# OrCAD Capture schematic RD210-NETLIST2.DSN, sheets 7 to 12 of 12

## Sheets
7 6: size Custom
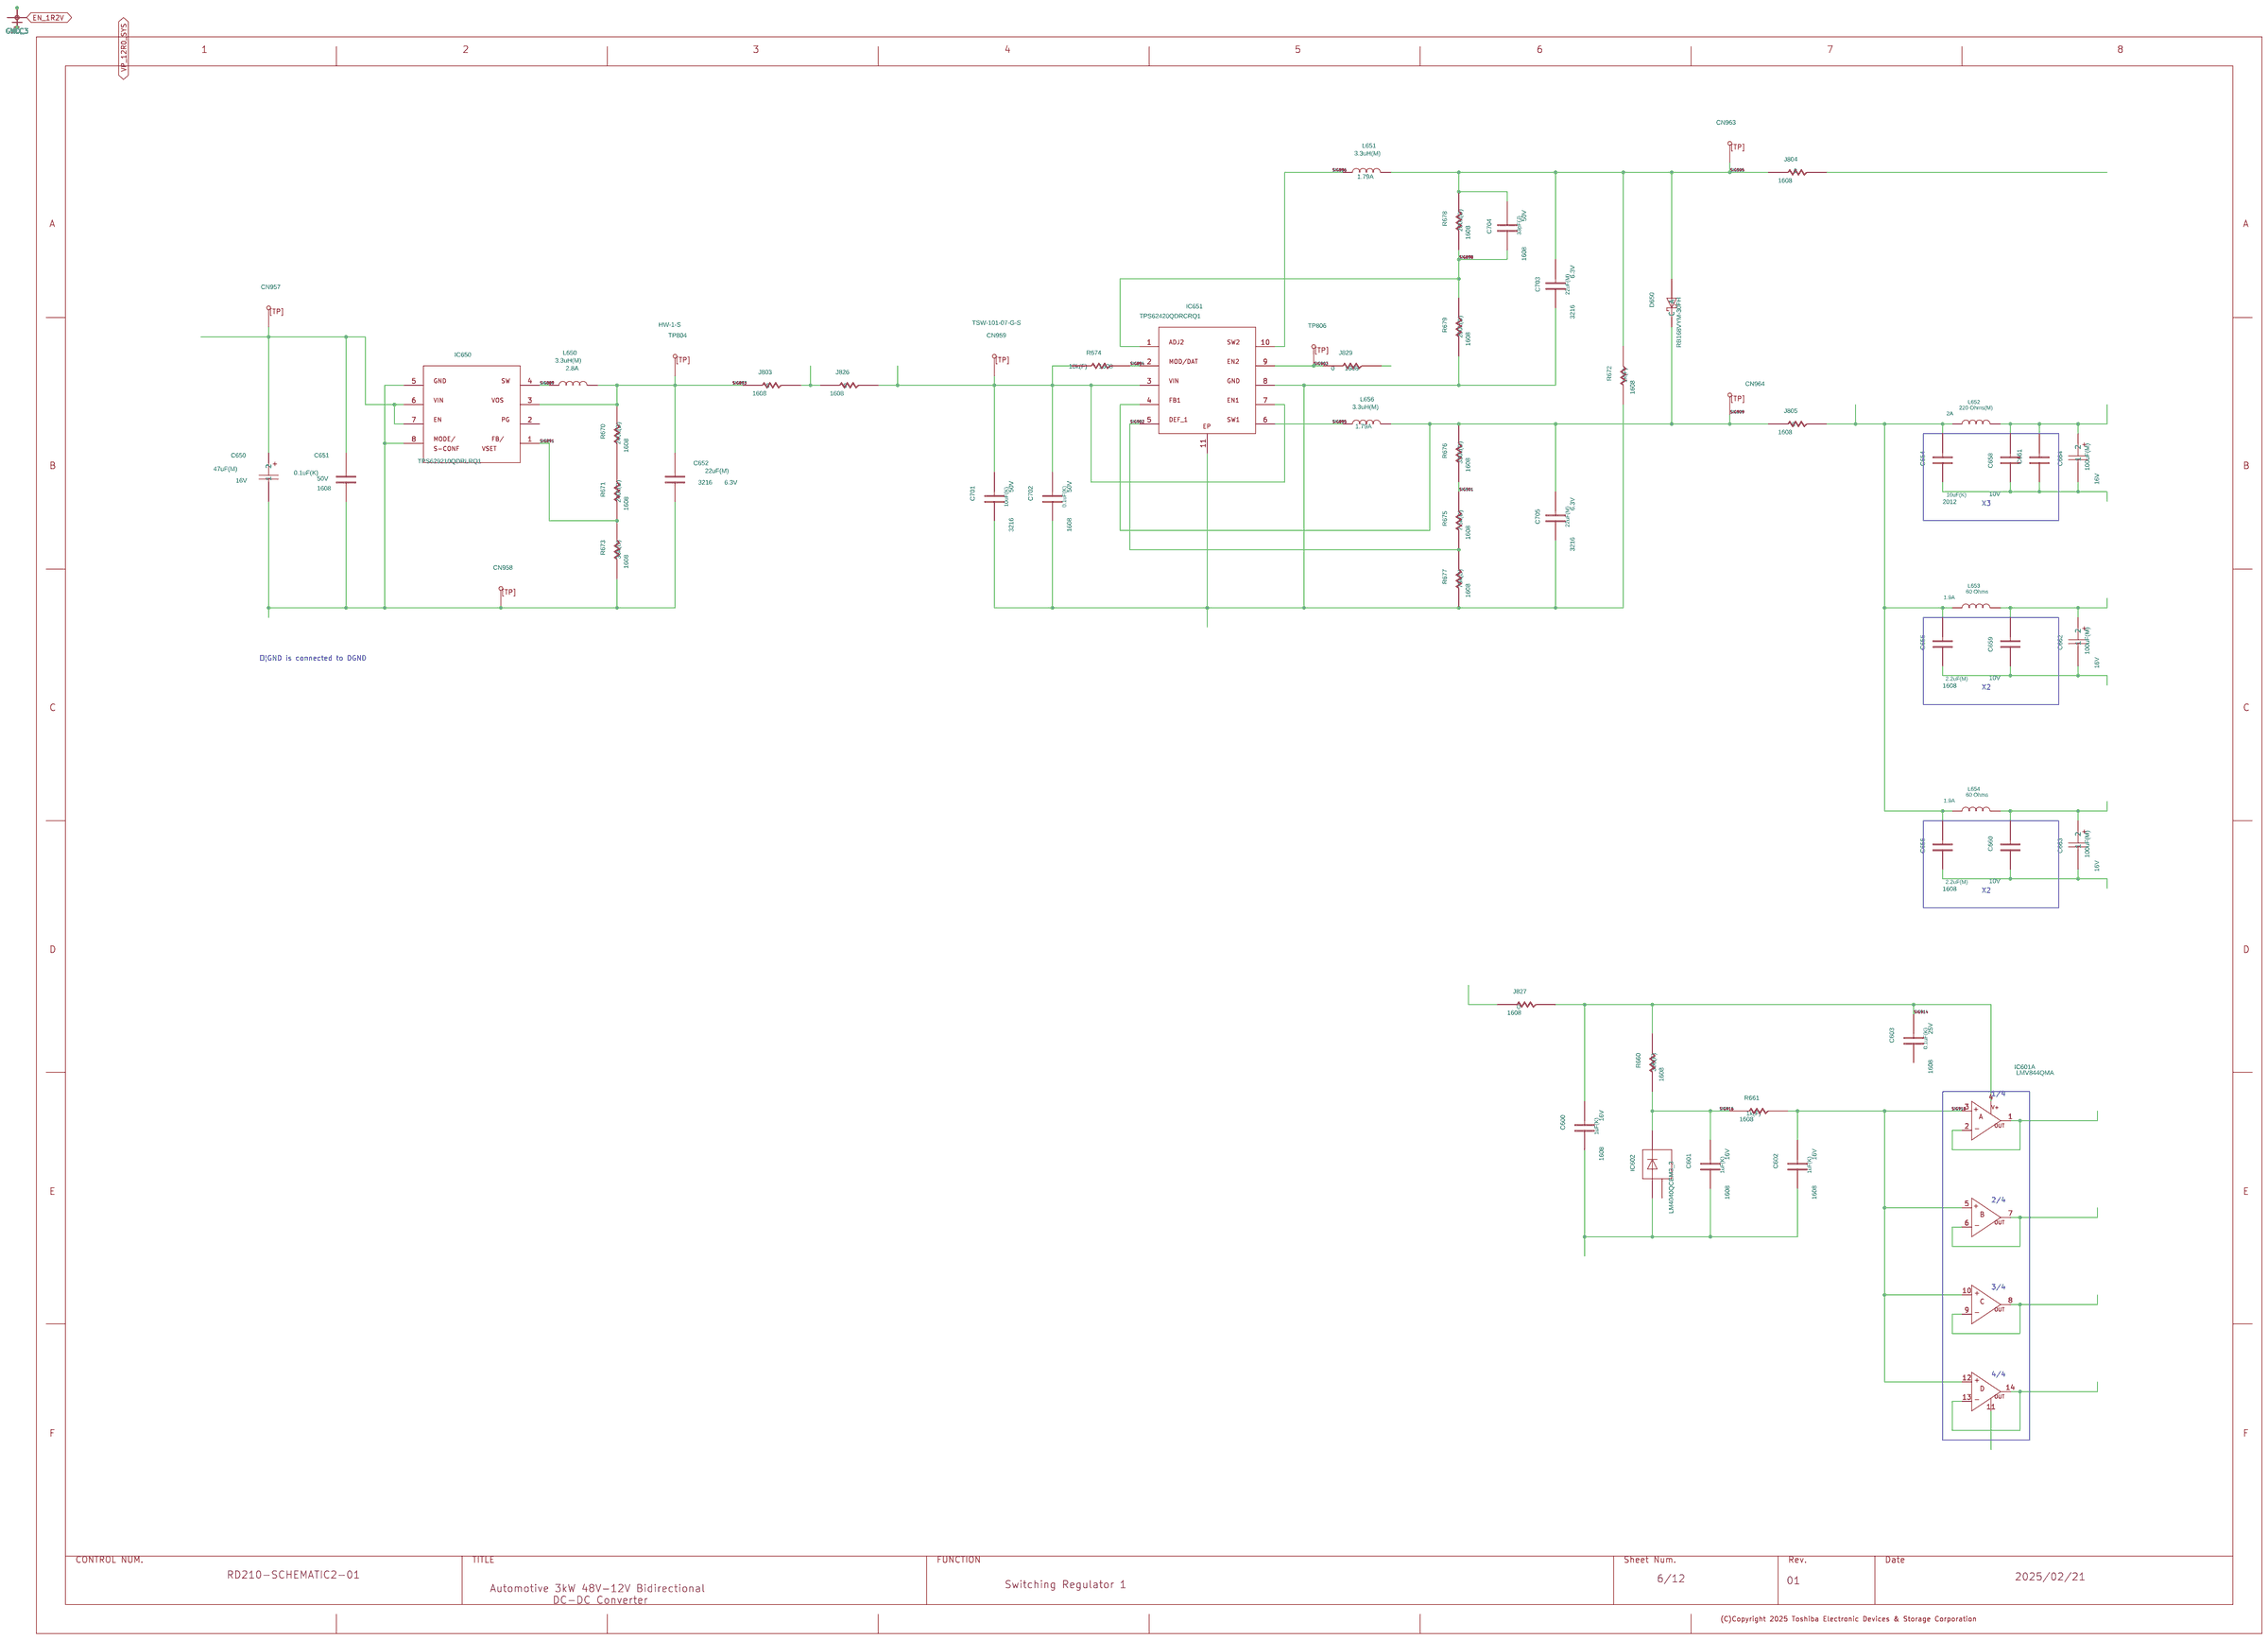
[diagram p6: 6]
8 5: size Custom
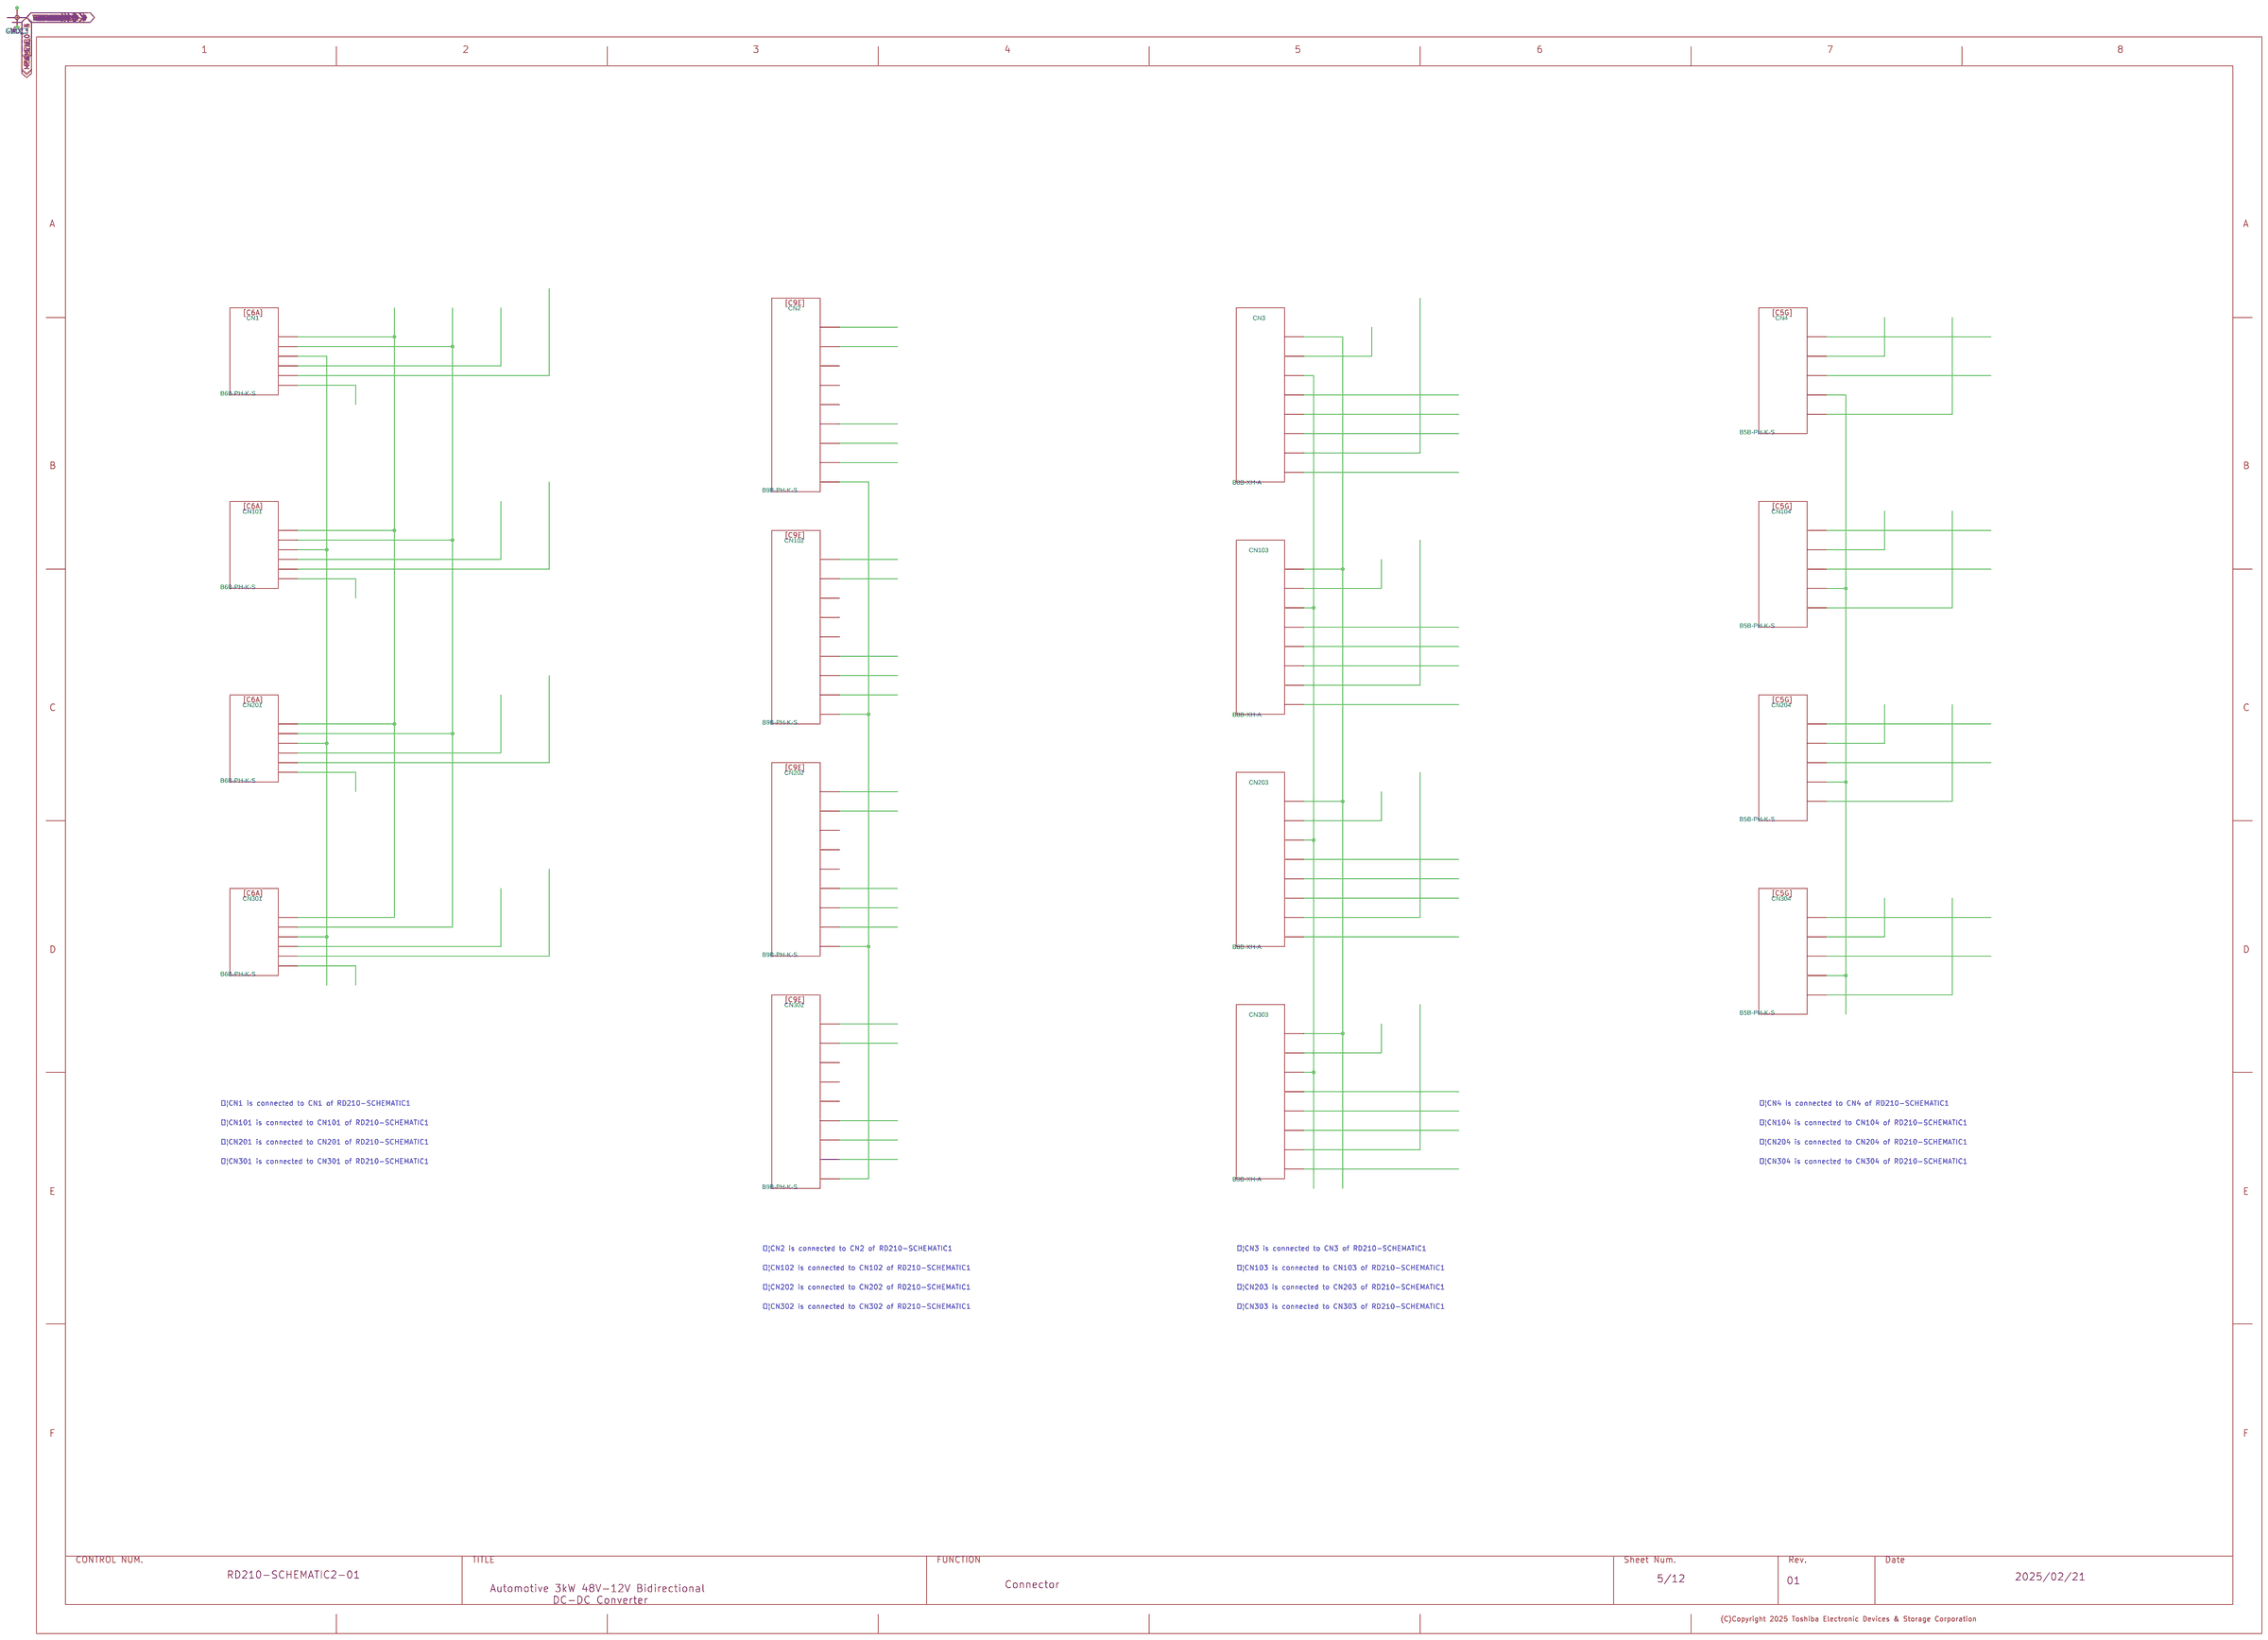
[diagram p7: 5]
9 4: size Custom
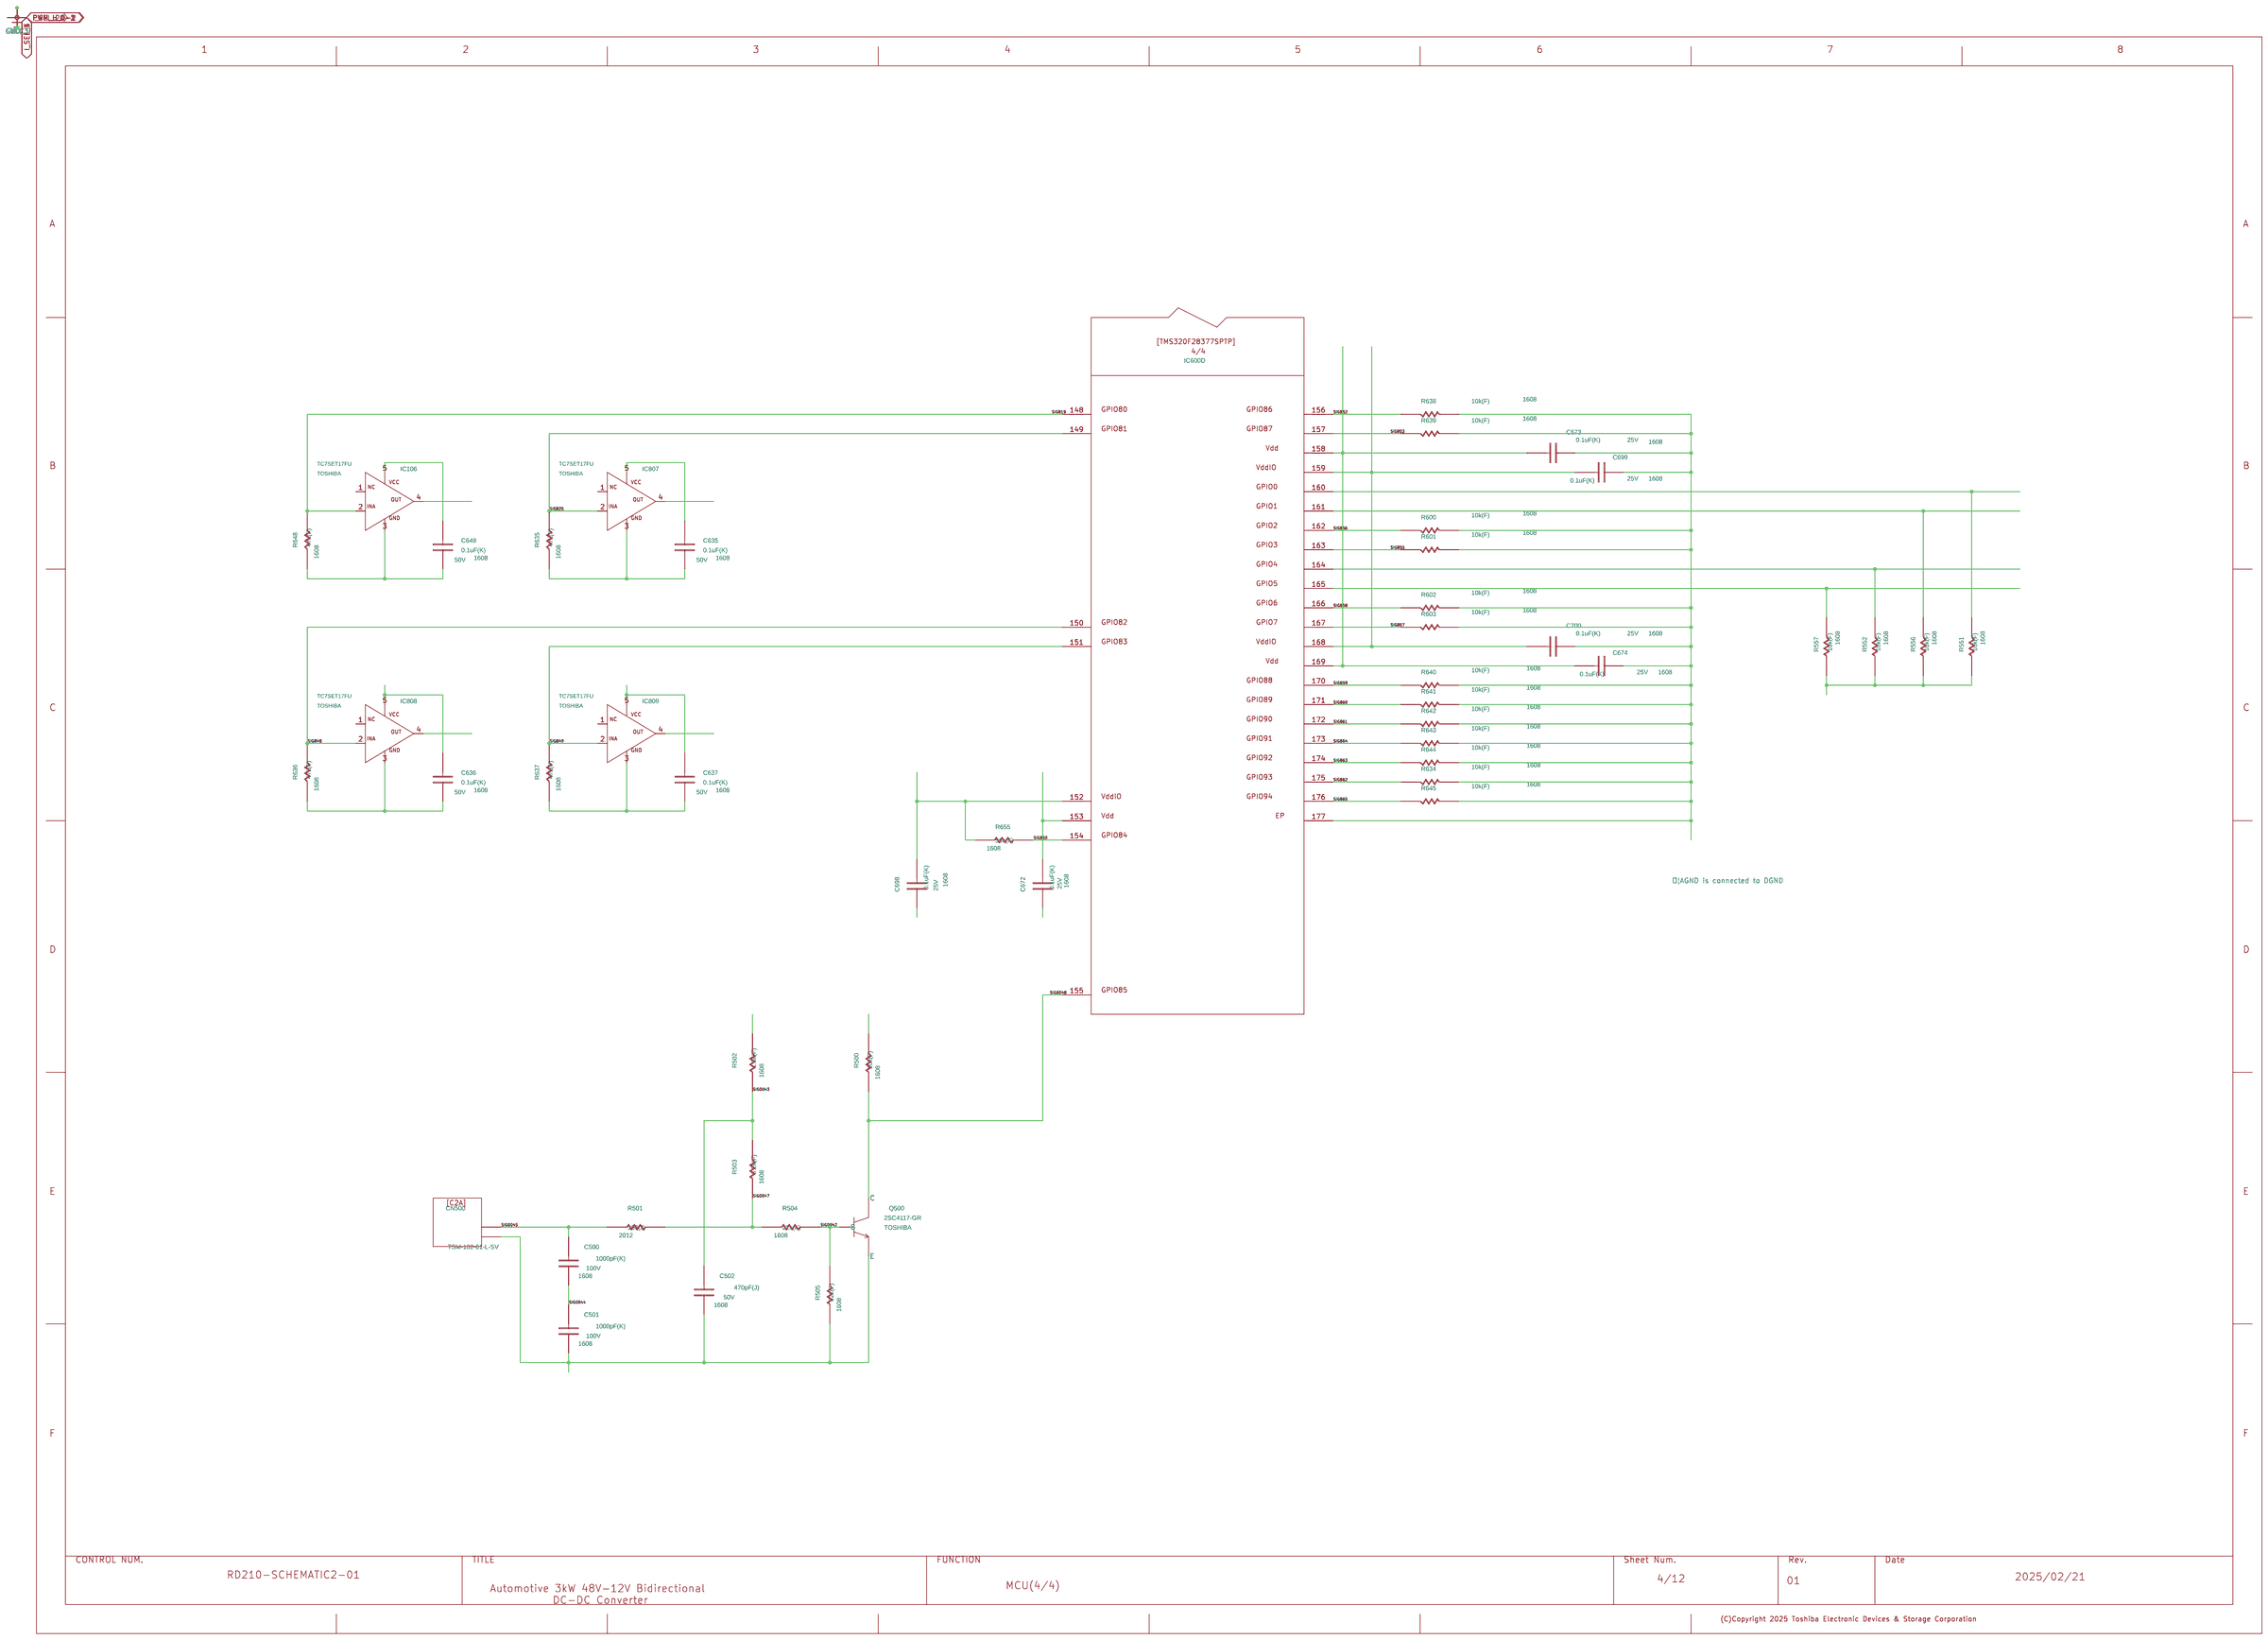
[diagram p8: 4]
10 3: size Custom
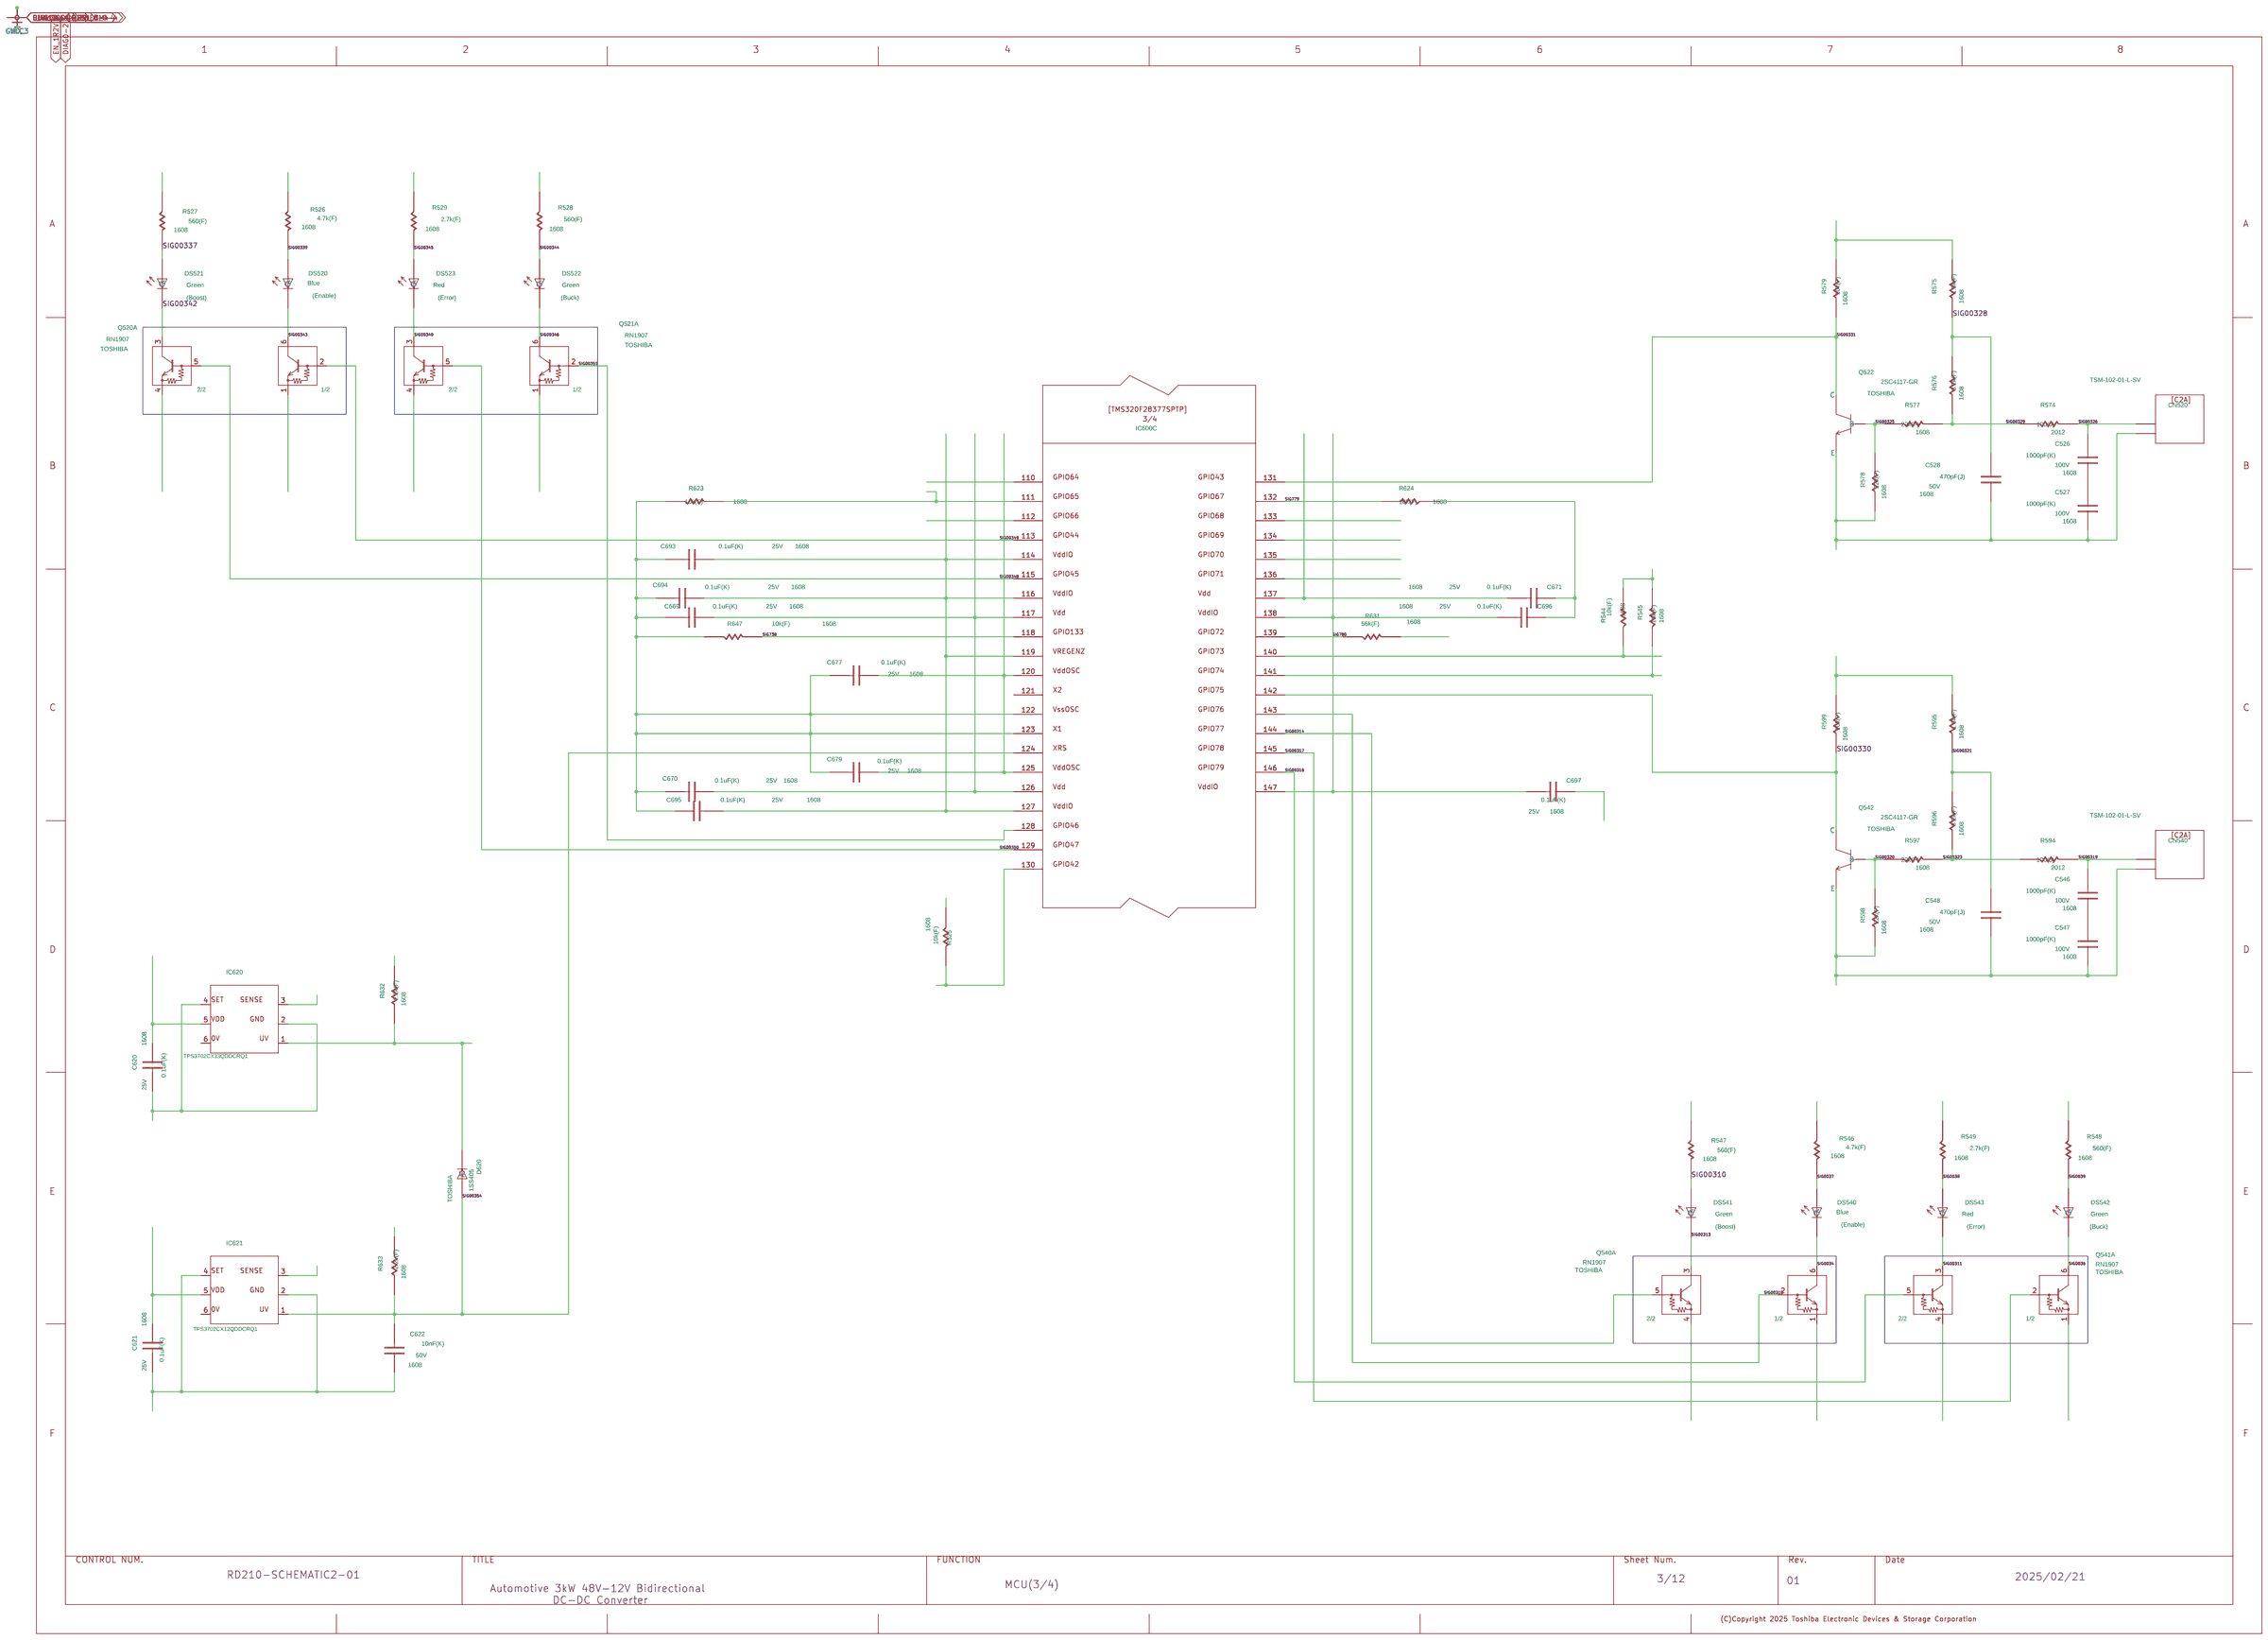
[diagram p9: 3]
11 2: size Custom
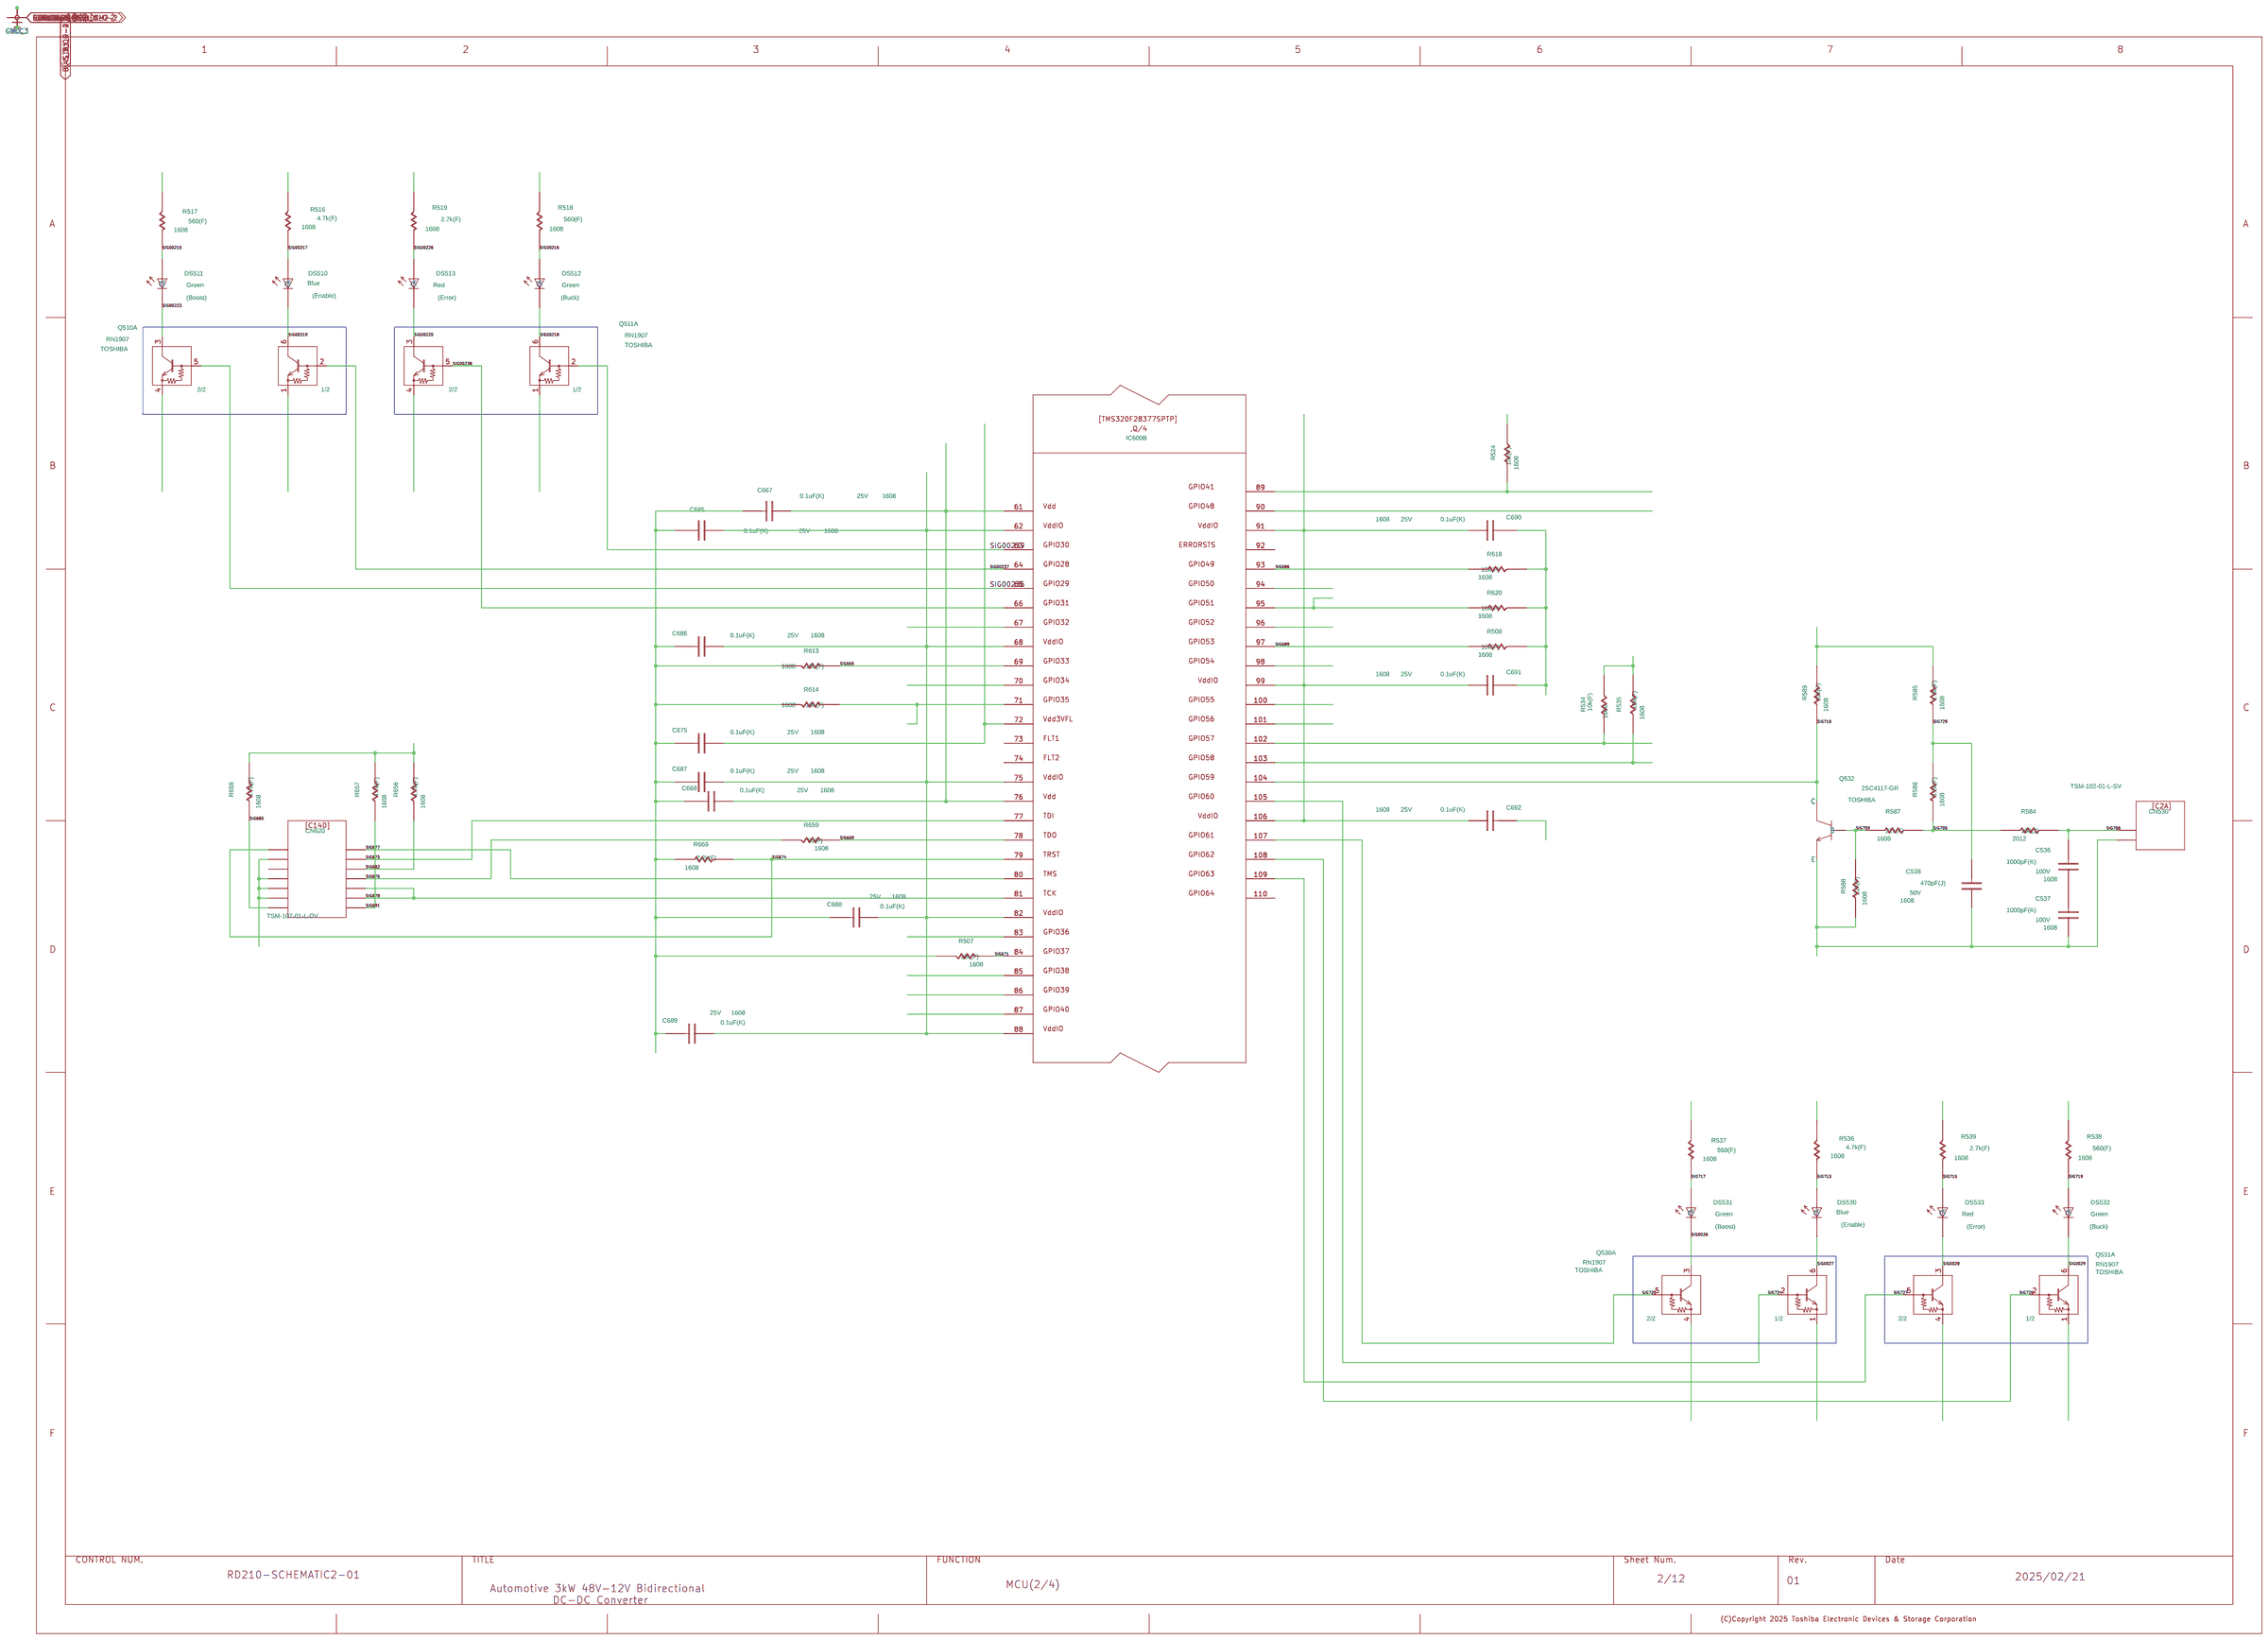
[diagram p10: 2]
12 1: size Custom
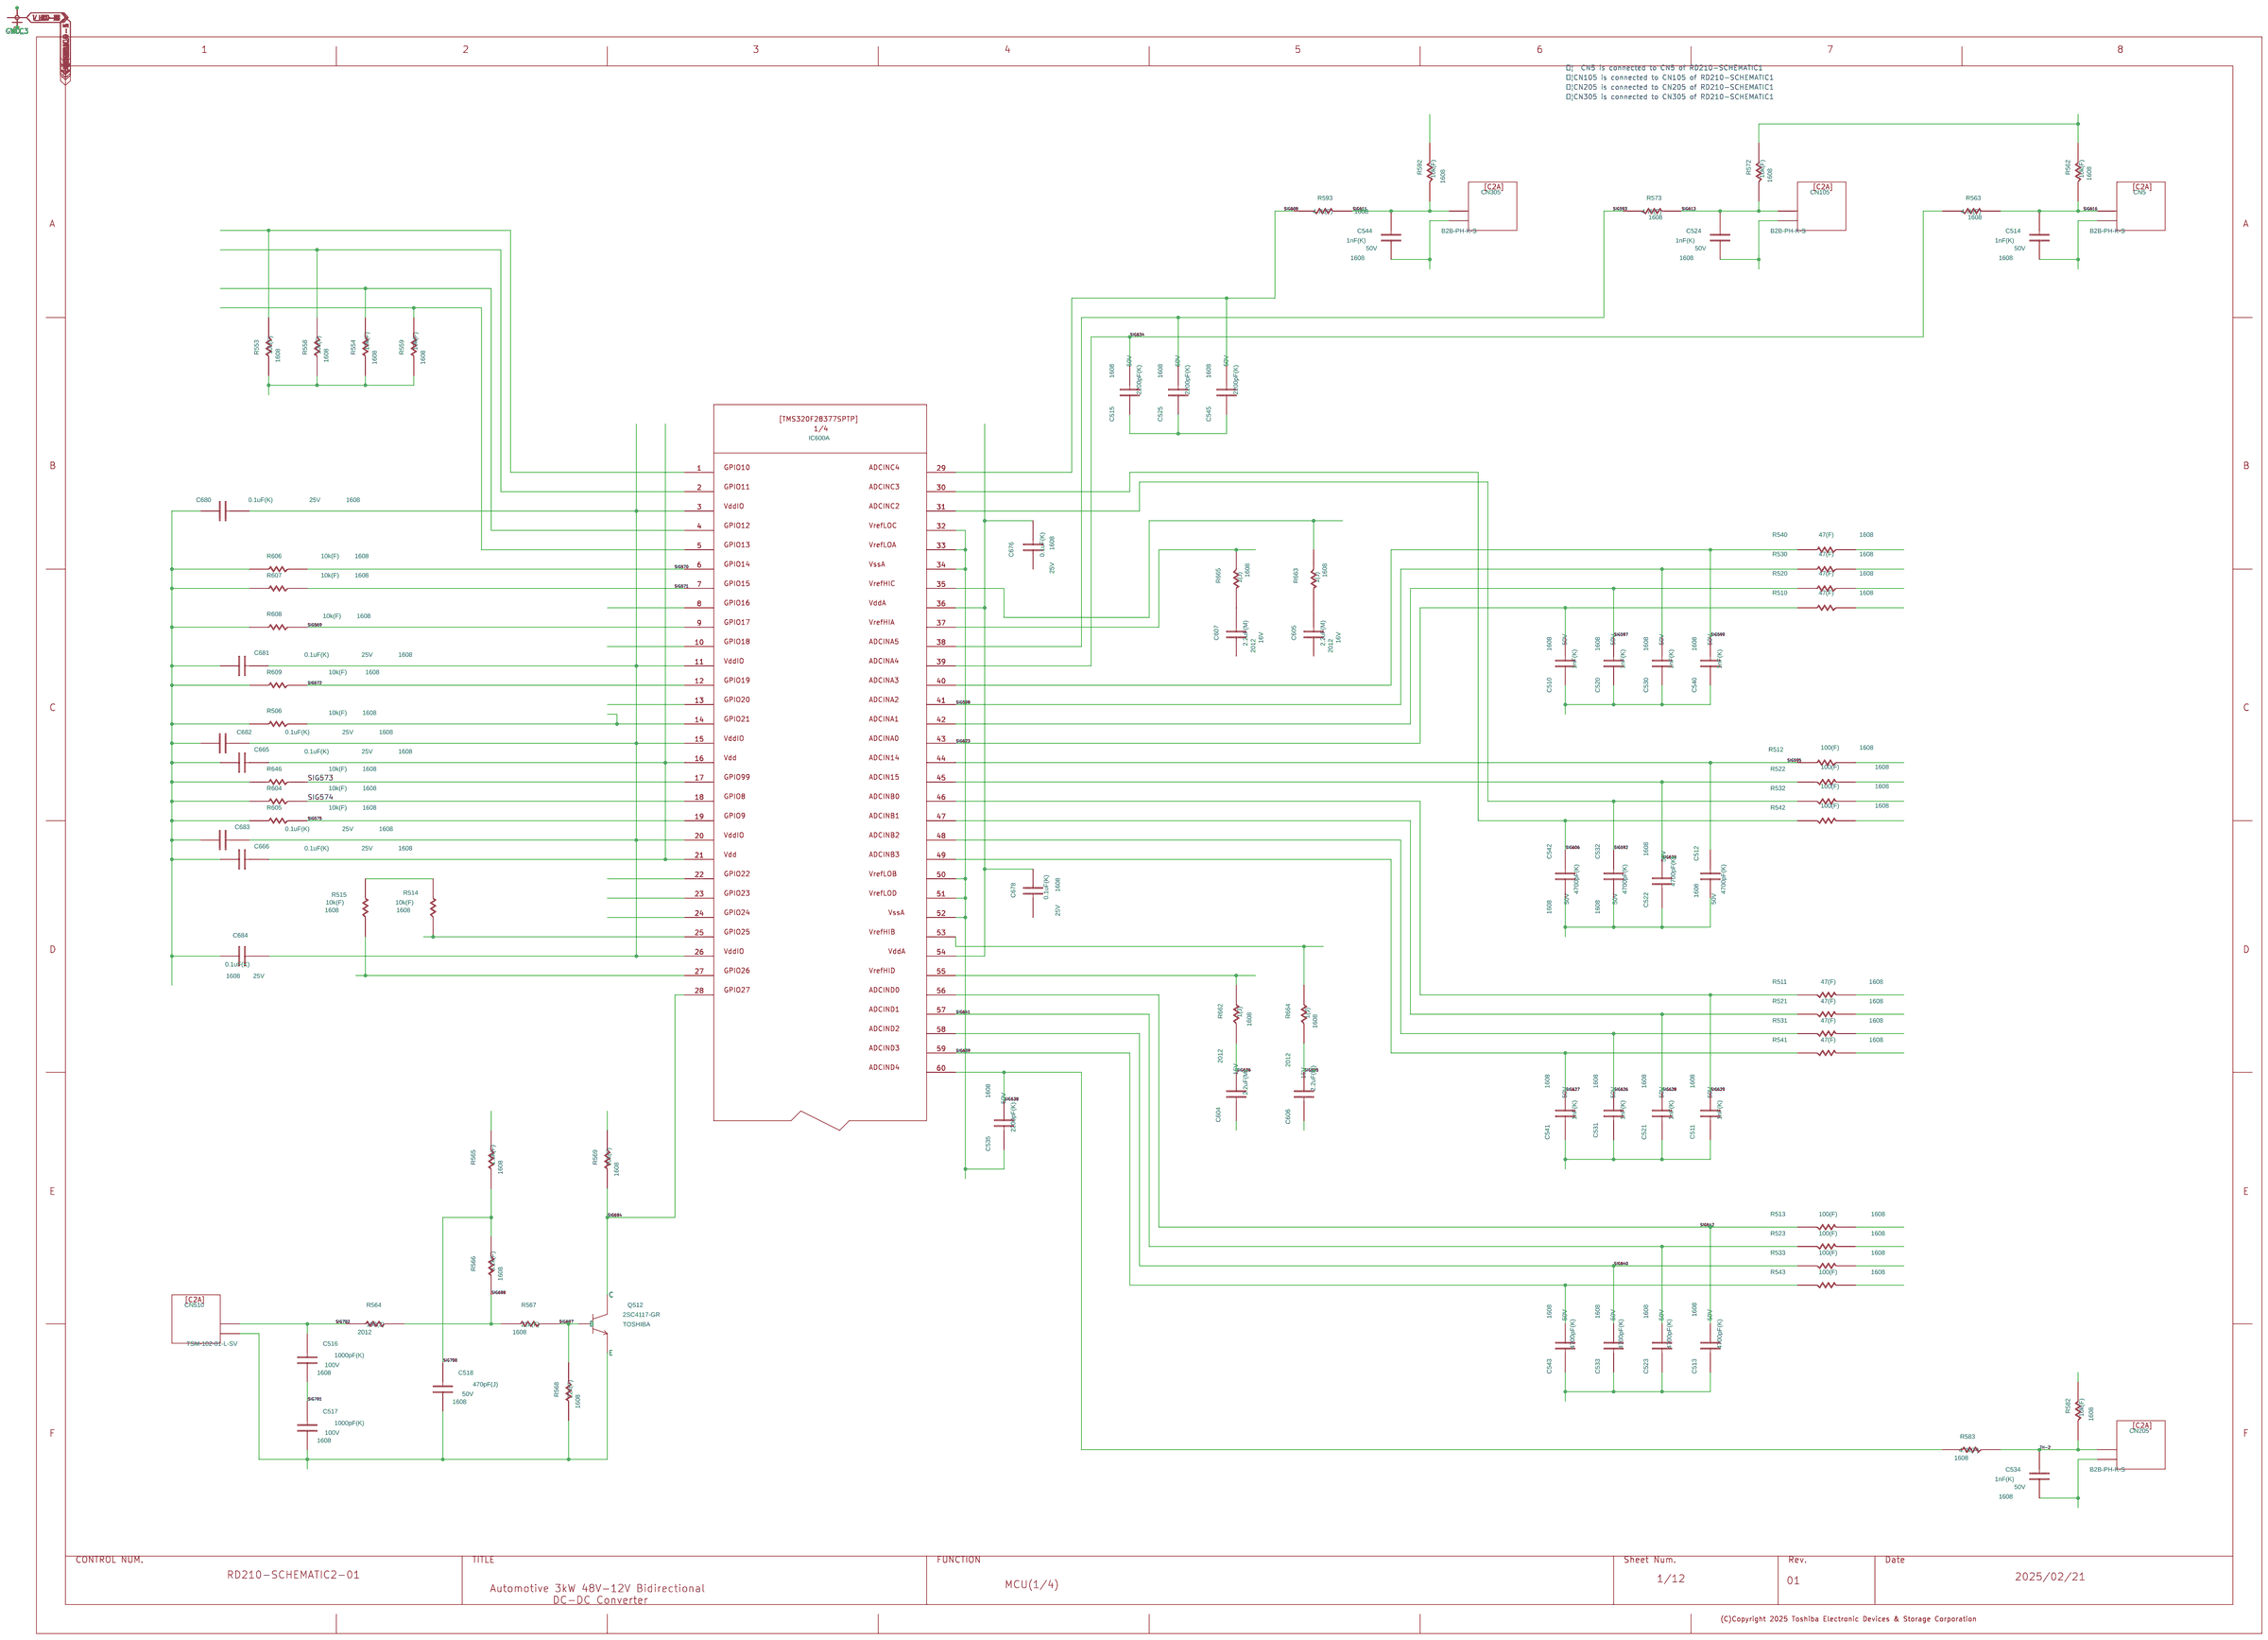
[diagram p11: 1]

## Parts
sheet 1
C510  C
C511  C
C512  C
C513  C
C514  C
C515  C
C516  C
C517  C
C518  C
C520  C
C521  C
C522  C
C523  C
C524  C
C525  C
C530  C
C531  C
C532  C
C533  C
C534  C
C535  C
C540  C
C541  C
C542  C
C543  C
C544  C
C545  C
C604  C
C605  C
C606  C
C607  C
C665  C
C666  C
C676  C
C678  C
C680  C
C681  C
C682  C
C683  C
C684  C
CN5  C2A
CN105  C2A
CN205  C2A
CN305  C2A
CN510  C2A
Q512  TRN
R506  R
R510  R
R511  R
R512  R
R513  R
R514  R
R515  R
R520  R
R521  R
R522  R
R523  R
R530  R
R531  R
R532  R
R533  R
R540  R
R541  R
R542  R
R543  R
R553  R
R554  R
R558  R
R559  R
R562  R
R563  R
R564  R
R565  R
R566  R
R567  R
R568  R
R569  R
R572  R
R573  R
R582  R
R583  R
R592  R
R593  R
R604  R
R605  R
R606  R
R607  R
R608  R
R609  R
R646  R
R662  R
R663  R
R664  R
R665  R
U?#11  WAKU_DEF_A3
sheet 2
C536  C
C537  C
C538  C
C667  C
C668  C
C675  C
C685  C
C686  C
C687  C
C688  C
C689  C
C690  C
C691  C
C692  C
CN530  C2A
CN620  C14D
DS510  LED
DS511  LED
DS512  LED
DS513  LED
DS530  LED
DS531  LED
DS532  LED
DS533  LED
Q510  RN1907_Q1  (sections A,B)
Q511  RN1907_Q1  (sections A,B)
Q530  RN1907_Q1  (sections A,B)
Q531  RN1907_Q1  (sections A,B)
Q532  TRN
R507  R
R508  R
R516  R
R517  R
R518  R
R519  R
R524  R
R534  R
R535  R
R536  R
R537  R
R538  R
R539  R
R584  R
R585  R
R586  R
R587  R
R588  R
R589  R
R613  R
R614  R
R618  R
R620  R
R656  R
R657  R
R658  R
R659  R
R669  R
U?#10  WAKU_DEF_A3
sheet 3
C526  C
C527  C
C528  C
C546  C
C547  C
C548  C
C620  C
C621  C
C622  C
C669  C
C670  C
C671  C
C677  C
C679  C
C693  C
C694  C
C695  C
C696  C
C697  C
CN520  C2A
CN540  C2A
D620  D
DS520  LED
DS521  LED
DS522  LED
DS523  LED
DS540  LED
DS541  LED
DS542  LED
DS543  LED
IC620  TPS3702CX12QDDCRQ1
IC621  TPS3702CX12QDDCRQ1
Q520  RN1907_Q1  (sections A,B)
Q521  RN1907_Q1  (sections A,B)
Q522  TRN
Q540  RN1907_Q1  (sections A,B)
Q541  RN1907_Q1  (sections A,B)
Q542  TRN
R525  R
R526  R
R527  R
R528  R
R529  R
R544  R
R545  R
R546  R
R547  R
R548  R
R549  R
R574  R
R575  R
R576  R
R577  R
R578  R
R579  R
R594  R
R595  R
R596  R
R597  R
R598  R
R599  R
R623  R
R624  R
R631  R
R632  R
R633  R
R647  R
U?#9  WAKU_DEF_A3
sheet 4
C500  C
C501  C
C502  C
C635  C
C636  C
C637  C
C648  C
C672  C
C673  C
C674  C
C698  C
C699  C
C700  C
CN500  C2A
IC106  TC7SET17FU
IC600  TMS320F28377SPTP_1  (sections A,B,C,D)
IC807  TC7SET17FU
IC808  TC7SET17FU
IC809  TC7SET17FU
Q500  TRN
R500  R
R501  R
R502  R
R503  R
R504  R
R505  R
R551  R
R552  R
R556  R
R557  R
R600  R
R601  R
R602  R
R603  R
R634  R
R635  R
R636  R
R637  R
R638  R
R639  R
R640  R
R641  R
R642  R
R643  R
R644  R
R645  R
R648  R
R655  R
U?#8  WAKU_DEF_A3
sheet 5
CN1  C6A
CN2  C9E
CN3  B8B-XH-A
CN4  C5G
CN101  C6A
CN102  C9E
CN103  B8B-XH-A
CN104  C5G
CN201  C6A
CN202  C9E
CN203  B8B-XH-A
CN204  C5G
CN301  C6A
CN302  C9E
CN303  B8B-XH-A
CN304  C5G
U?#7  WAKU_DEF_A3
sheet 6
C600  C
C601  C
C602  C
C603  C
C650  CP
C651  C
C652  C
C654  C
C655  C
C656  C
C658  C
C659  C
C660  C
C661  C
C662  CP
C663  CP
C664  CP
C701  C
C702  C
C703  C
C704  C
C705  C
CN957  TP
CN958  TP
CN959  TP
CN963  TP
CN964  TP
D650  SBD
IC601  LMV844QMA_1  (sections A,B,C,D)
IC602  LM4040QCEM3_3
IC650  TPS629210QDRLRQ1
IC651  TPS62420QDRCRQ1
J803  R
J804  R
J805  R
J826  R
J827  R
J829  R
L650  L
L651  L
L652  L
L653  L
L654  L
L656  L
R660  R
R661  R
R670  R
R671  R
R672  R
R673  R
R674  R
R675  R
R676  R
R677  R
R678  R
R679  R
TP804  TP
TP806  TP
U?#6  WAKU_DEF_A3

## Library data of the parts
C510 C511 C514 C520 C521 C524 C530 C531 C534 C540 C541 C544 = C: COMPONENTTYPE: 4; SIZECODESMD: 1608; VAL1: 1nF(K); VAL2: 50V
C512 C513 C522 C523 C532 C533 C542 C543 = C: COMPONENTTYPE: 4; SIZECODESMD: 1608; VAL1: 4700pF(K); VAL2: 50V
C515 C525 C535 C545 = C: COMPONENTTYPE: 4; SIZECODESMD: 1608; VAL1: 2200pF(K); VAL2: 50V
C500 C501 C516 C517 C526 C527 C536 C537 C546 C547 = C: COMPONENTTYPE: 4; SIZECODESMD: 1608; VAL1: 1000pF(K); VAL2: 100V
C502 C518 C528 C538 C548 = C: COMPONENTTYPE: 4; SIZECODESMD: 1608; VAL1: 470pF(J); VAL2: 50V
C604-C607 = C: COMPONENTTYPE: 4; SIZECODESMD: 2012; VAL1: 2.2uF(M); VAL2: 16V
C603 C620 C621 C665-C700 = C: COMPONENTTYPE: 4; SIZECODESMD: 1608; VAL1: 0.1uF(K); VAL2: 25V
CN5 CN105 CN205 CN305 = C2A: CDBNAME: CN; COMP: CN; COMPONENTTYPE: 4; VAL3: B2B-PH-K-S
CN500 CN510 CN520 CN530 CN540 = C2A: CDBNAME: CN; COMP: CN; COMPONENTTYPE: 4; VAL3: TSM-102-01-L-SV
Q500 Q512 Q522 Q532 Q542 = TRN: CDBNAME: Q; COMP: Q; COMPONENTTYPE: 4; USERCOMPTEXT3: TOSHIBA; VAL3: 2SC4117-GR
R500 R506-R508 R514 R515 R524 R525 R534 R535 R544 R545 R551-R554 R556-R559 R562 R569 R572 R579 R582 R589 R592 R599-R609 R613 R614 R618 R620 R623 R624 R634 R638-R647 R674 = R: COMPONENTTYPE: 4; SIZECODESMD: 1608; VAL1: 10k(F); VAL2: 200mW
R510 R511 R520 R521 R530 R531 R540 R541 = R: COMPONENTTYPE: 4; SIZECODESMD: 1608; VAL1: 47(F); VAL2: 200mW
R512 R513 R522 R523 R532 R533 R542 R543 = R: COMPONENTTYPE: 4; SIZECODESMD: 1608; VAL1: 100(F); VAL2: 200mW
R516 R526 R536 R546 R563 R573 R583 R593 R656-R658 = R: COMPONENTTYPE: 4; SIZECODESMD: 1608; VAL1: 4.7k(F); VAL2: 200mW
R501 R564 R574 R584 R594 = R: COMPONENTTYPE: 4; SIZECODESMD: 2012; VAL1: 100(J); VAL2: 250mW
R502 R565 R575 R585 R595 = R: COMPONENTTYPE: 4; SIZECODESMD: 1608; VAL1: 1.8k(F); VAL2: 333mW
R503 R566 R576 R586 R596 = R: COMPONENTTYPE: 4; SIZECODESMD: 1608; VAL1: 8.2k(F); VAL2: 333mW
R504 R505 R567 R568 R577 R578 R587 R588 R597 R598 = R: COMPONENTTYPE: 4; SIZECODESMD: 1608; VAL1: 22k(F); VAL2: 333mW
R662-R665 = R: COMPONENTTYPE: 4; SIZECODESMD: 1608; VAL1: 1(J); VAL2: 125mW
U?#11 = WAKU_DEF_A3: COMPONENTTYPE: 2; DATE: 2025/02/21; DRAWINGNUMBER: RD210-SCHEMATIC2-01; FUNCTION: MCU(1/4); REVISION: 01; SAVEAREA0: 185750,-43960,448537,75779; SAVECOUNT: 19; SHEETNUMBER: 1/12; SHTSAVECOUNT: 205; TITLE: Automotive 3kW 48V-12V Bidirectional / DC-DC Converter; UPDATEDATE: 2025.2.21; UPDATETIME: 06:59:19
CN620 = C14D: CDBNAME: CN; COMP: CN; COMPONENTTYPE: 4; VAL3: TSM-107-01-L-DV
DS510 DS520 DS530 DS540 = LED: CDBNAME: DS; COMP: DS; COMPONENTTYPE: 4; USERCOMPTEXT1: (Enable); VAL1: Blue; VAL3: KB_DELPS2.12
DS511 DS521 DS531 DS541 = LED: CDBNAME: DS; COMP: DS; COMPONENTTYPE: 4; USERCOMPTEXT1: (Boost); VAL1: Green; VAL3: KT_DELQS1.12
DS512 DS522 DS532 DS542 = LED: CDBNAME: DS; COMP: DS; COMPONENTTYPE: 4; USERCOMPTEXT1: (Buck); VAL1: Green; VAL3: KT_DELQS1.12
DS513 DS523 DS533 DS543 = LED: CDBNAME: DS; COMP: DS; COMPONENTTYPE: 4; USERCOMPTEXT1: (Error); VAL1: Red; VAL3: KS_DELQS1.12
Q510 Q520 Q521 Q540 Q541 = RN1907_Q1: CDBNAME: RN1907; COMP: RN1907; COMPONENTNAME: RN1907_1; COMPONENTTYPE: 8; CaptureCellPackProp: RN1907_Q1A; FUNCN: RN1907_1; USERCOMPTEXT1: 1/2; USERCOMPTEXT3: TOSHIBA; VAL3: RN1907
Q511 = RN1907_Q1: CDBNAME: RN1907; COMP: RN1907; COMPONENTNAME: RN1907_2; COMPONENTTYPE: 8; CaptureCellPackProp: RN1907_Q1B; FUNCN: RN1907_2; USERCOMPTEXT1: 2/2; USERCOMPTEXT3: TOSHIBA; VAL3: RN1907
Q530 Q531 = RN1907_Q1: CDBNAME: RN1907; COMP: RN1907; COMPONENTKIND: 101; COMPONENTNAME: RN1907_1; COMPONENTTYPE: 8; CaptureCellPackProp: RN1907_Q1A; FUNCN: RN1907_1; USERCOMPTEXT1: 1/2; USERCOMPTEXT3: TOSHIBA; VAL3: RN1907
R517 R518 R527 R528 R537 R538 R547 R548 = R: COMPONENTTYPE: 4; SIZECODESMD: 1608; VAL1: 560(F); VAL2: 200mW
R519 R529 R539 R549 = R: COMPONENTTYPE: 4; SIZECODESMD: 1608; VAL1: 2.7k(F); VAL2: 200mW
R659 = R: COMPONENTTYPE: 4; SIZECODESMD: 1608; VAL1: 39(F); VAL2: 200mW
R632 R633 R669 = R: COMPONENTTYPE: 4; SIZECODESMD: 1608; VAL1: 2.2k(F); VAL2: 200mW
U?#10 = WAKU_DEF_A3: AUTHOR: sptcae13; COMPONENTTYPE: 2; DATE: 2025/02/21; DRAWINGNUMBER: RD210-SCHEMATIC2-01; FUNCTION: MCU(2/4); REVISION: 01; SAVECOUNT: 19; SHEETNUMBER: 2/12; SHTSAVECOUNT: 79; TIME: 08:03:34; TITLE: Automotive 3kW 48V-12V Bidirectional / DC-DC Converter; UPDATEDATE: 2025.2.21; UPDATETIME: 13:38:15
C622 = C: COMPONENTTYPE: 4; SIZECODESMD: 1608; VAL1: 10nF(K); VAL2: 50V
D620 = D: COMPONENTTYPE: 4; USERCOMPTEXT3: TOSHIBA; VAL3: 1SS405
IC620 = TPS3702CX12QDDCRQ1: CDBNAME: IC; COMP: IC; COMPONENTKIND: 101; COMPONENTTYPE: 4; VAL3: TPS3702CX33QDDCRQ1
IC621 = TPS3702CX12QDDCRQ1: CDBNAME: IC; COMP: IC; COMPONENTKIND: 101; COMPONENTTYPE: 4
R631 R655 = R: COMPONENTTYPE: 4; SIZECODESMD: 1608; VAL1: 56k(F); VAL2: 200mW
U?#9 = WAKU_DEF_A3: AUTHOR: sptcae13; COMPONENTTYPE: 2; DATE: 2025/02/21; DRAWINGNUMBER: RD210-SCHEMATIC2-01; FUNCTION: MCU(3/4); REVISION: 01; SAVECOUNT: 19; SHEETNUMBER: 3/12; SHTSAVECOUNT: 66; TIME: 08:03:34; TITLE: Automotive 3kW 48V-12V Bidirectional / DC-DC Converter; UPDATEDATE: 2025.2.21; UPDATETIME: 12:28:01
C635-C637 C648 C651 C702 = C: COMPONENTTYPE: 4; SIZECODESMD: 1608; VAL1: 0.1uF(K); VAL2: 50V
IC106 IC807-IC809 = TC7SET17FU: CDBNAME: IC; COMP: IC; COMPONENTTYPE: 4; USERCOMPTEXT3: TOSHIBA
IC600 = TMS320F28377SPTP_1: CDBNAME: IC; COMP: IC; COMPONENTTYPE: 8; CaptureCellPackProp: TMS320F28377SPTP_1A; SAVEAREA0: -164425,-192040,236003,1269; USERCOMPTEXT3: TOSHIBA; VAL3: TMS320F28377SPTP; SAVECOUNT: 25
R635-R637 R648 = R: COMPONENTTYPE: 4; SIZECODESMD: 1608; VAL1: 47k(F); VAL2: 100mW
U?#8 = WAKU_DEF_A3: AUTHOR: sptcae13; COMPONENTTYPE: 2; DATE: 2025/02/21; DRAWINGNUMBER: RD210-SCHEMATIC2-01; FUNCTION: MCU(4/4); REVISION: 01; SAVECOUNT: 8; SHEETNUMBER: 4/12; SHTSAVECOUNT: 41; TIME: 17:43:31; TITLE: Automotive 3kW 48V-12V Bidirectional / DC-DC Converter; UPDATEDATE: 2025.2.21; UPDATETIME: 06:43:32
CN1 CN101 CN201 CN301 = C6A: CDBNAME: CN; COMP: CN; COMPONENTTYPE: 4; VAL3: B6B-PH-K-S
CN2 CN102 CN202 CN302 = C9E: CDBNAME: CN; COMP: CN; COMPONENTTYPE: 4; VAL3: B9B-PH-K-S
CN3 CN103 CN203 CN303 = B8B-XH-A: CDBNAME: CN; COMP: CN; COMPONENTTYPE: 4
CN4 CN104 CN204 CN304 = C5G: CDBNAME: CN; COMP: CN; COMPONENTTYPE: 4; VAL3: B5B-PH-K-S
U?#7 = WAKU_DEF_A3: AUTHOR: sptcae13; COMPONENTTYPE: 2; DATE: 2025/02/21; DRAWINGNUMBER: RD210-SCHEMATIC2-01; FUNCTION: Connector; REVISION: 01; SAVEAREA0: -45080,-4508,463680,304612; SAVECOUNT: 19; SHEETNUMBER: 5/12; SHTSAVECOUNT: 33; TIME: 09:45:21; TITLE: Automotive 3kW 48V-12V Bidirectional / DC-DC Converter; UPDATEDATE: 2025.2.21; UPDATETIME: 09:54:21
C600-C602 = C: COMPONENTTYPE: 4; SIZECODESMD: 1608; VAL1: 1uF(K); VAL2: 16V
C650 = CP: ADSCNVFLAG: ON; CDBNAME: C; COMP: C; COMPONENTTYPE: 4; GCOUNT: 1; ICX_PART_MODEL: CON_47U; MAXGCOUNT: 1; SQ_PART_MODEL: CON_47U; VAL1: 47uF(M); VAL2: 16V
C652 C703 C705 = C: COMPONENTTYPE: 4; SIZECODESMD: 3216; VAL1: 22uF(M); VAL2: 6.3V
C654 C658 C661 = C: COMPONENTTYPE: 4; SIZECODESMD: 2012; VAL1: 10uF(K); VAL2: 10V
C655 C656 C659 C660 = C: COMPONENTTYPE: 4; SIZECODESMD: 1608; VAL1: 2.2uF(M); VAL2: 10V
C662-C664 = CP: CDBNAME: C; COMP: C; COMPONENTTYPE: 4; VAL1: 100uF(M); VAL2: 16V
C701 = C: COMPONENTTYPE: 4; SIZECODESMD: 3216; VAL1: 10uF(K); VAL2: 50V
C704 = C: COMPONENTTYPE: 4; SIZECODESMD: 1608; VAL1: 33pF(J); VAL2: 50V
CN957-CN959 CN963 CN964 = TP: CDBNAME: CN; COMP: CN; COMPONENTTYPE: 4; VAL3: TSW-101-07-G-S
D650 = SBD: CDBNAME: D; COMP: D; COMPONENTTYPE: 4; VAL3: RB168VYM-30FH
IC601 = LMV844QMA_1: CDBNAME: LMV844QMA; COMP: LMV844QMA; COMPONENTTYPE: 8; CaptureCellPackProp: LMV844QMA_1A; VAL3: LMV844QMA; SAVEAREA0: -10101,-18267,23348,18085
IC602 = LM4040QCEM3_3: CDBNAME: IC; COMP: IC; COMPONENTTYPE: 4
IC650 = TPS629210QDRLRQ1: CDBNAME: IC; COMP: IC; COMPONENTTYPE: 4
IC651 = TPS62420QDRCRQ1: CDBNAME: IC; COMP: IC; COMPONENTTYPE: 4
J803-J805 J826 J827 J829 = R: CDBNAME: JP; COMP: JP; COMPONENTTYPE: 4; SIZECODESMD: 1608; VAL1: 0
L650 = L: COMPONENTTYPE: 4; VAL1: 3.3uH(M); VAL2: 2.8A; VAL3: XGL3520-332MEC
L651 L656 = L: COMPONENTTYPE: 4; VAL1: 3.3uH(M); VAL2: 1.79A; VAL3: VLS3015CX-3R3M-H
L652 = L: COMPONENTTYPE: 4; VAL1: 220 Ohms(M); VAL2: 2A; VAL3: BLM21PG221SN1D
L653 L654 = L: COMPONENTTYPE: 4; VAL1: 60 Ohms; VAL2: 1.9A; VAL3: BLM21PG600BH1
R660 = R: COMPONENTTYPE: 4; SIZECODESMD: 1608; VAL1: 300(F); VAL2: 200mW
R661 R672 = R: COMPONENTTYPE: 4; SIZECODESMD: 1608; VAL1: 1k(F); VAL2: 200mW
R670 R671 = R: COMPONENTTYPE: 4; SIZECODESMD: 1608; VAL1: 240k(D); VAL2: 200mW
R673 = R: COMPONENTTYPE: 4; SIZECODESMD: 1608; VAL1: 36k(D); VAL2: 200mW
R675 = R: COMPONENTTYPE: 4; SIZECODESMD: 1608; VAL1: 7.5k(D); VAL2: 200mW
R676 = R: COMPONENTTYPE: 4; SIZECODESMD: 1608; VAL1: 330k(D); VAL2: 200mW
R677 = R: COMPONENTTYPE: 4; SIZECODESMD: 1608; VAL1: 75k(D); VAL2: 200mW
R678 R679 = R: COMPONENTTYPE: 4; SIZECODESMD: 1608; VAL1: 200k(D); VAL2: 200mW
TP804 TP806 = TP: COMPONENTTYPE: 4; VAL3: HW-1-S
U?#6 = WAKU_DEF_A3: AUTHOR: sptcae13; COMPONENTTYPE: 2; DATE: 2025/02/21; DRAWINGNUMBER: RD210-SCHEMATIC2-01; FUNCTION: Switching Regulator 1; REVISION: 01; SAVECOUNT: 8; SHEETNUMBER: 6/12; SHTSAVECOUNT: 53; TIME: 13:37:44; TITLE: Automotive 3kW 48V-12V Bidirectional / DC-DC Converter; UPDATEDATE: 2025.2.21; UPDATETIME: 14:05:32

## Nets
AGND: C510.1 C511.2 C512.1 C513.2 C514.1 C515.1 C520.1 C521.2 C522.2 C523.2 C524.1 C525.1 C530.1 C531.2 C532.1 C533.2 C534.1 C535.2 C540.1 C541.2 C542.1 C543.2 C544.1 C545.1 C600.1 C601.1 C602.1 C603.1 C604.2 C605.1 C606.2 C607.1 C676.1 C678.2 CN5.2 CN105.2 CN205.2 CN305.2 IC600.32 IC600.33 IC600.34 IC600.50 IC600.51 IC600.52 IC601.11 IC602.2 R670.1 R671.2
DGND: C620.2 C621.2 C622.1 C654.1 C655.1 C656.1 C658.1 C659.1 C660.1 C661.1 C662.2(1) C663.2(1) C664.2(1) C665.1 C666.1 C667.2 C668.2 C669.2 C670.2 C671.1 C673.1 C674.1 C675.2 C677.2 C679.2 C680.1 C681.1 C682.1 C683.1 C684.1 C685.2 C686.2 C687.2 C688.2 C689.2 C690.2 C691.2 C692.2 C693.2 C694.2 C695.1 C696.1 C697.1 C699.1 C700.1 C701.1 C702.1 C703.1 C705.1 CN620.4 CN620.8 CN620.10 CN620.12 IC600.122 IC600.123 IC600.177 IC620.2 IC620.4 IC621.2 IC621.4 IC651.8 IC651.11 Q510.1 Q510.4 Q511.1 Q511.4 Q520.1 Q520.4 Q521.1 Q521.4 Q530.1 Q530.4 Q531.1 Q531.4 Q540.1 Q540.4 Q541.1 Q541.4 R506.1 R507.2 R508.2 R551.1 R552.1 R553.1 R554.1 R556.1 R557.1 R558.1 R559.1 R600.1 R601.1 R602.1 R603.1 R604.1 R605.1 R606.1 R607.1 R608.1 R609.1 R613.2 R614.2 R618.2 R620.2 R623.2 R624.2 R634.1 R638.1 R639.1 R640.1 R641.1 R642.1 R643.1 R644.1 R645.1 R646.1 R647.2 R669.1 R672.1 R677.1 R679.1
GND: C501.1 C502.1 C517.1 C518.1 C527.1 C528.1 C537.1 C538.1 C547.1 C548.1 C635.1 C636.1 C637.1 C648.1 C650.2(1) C651.1 C652.1 C672.1 C698.1 CN1.3 CN2.9 CN3.3 CN4.4 CN101.3 CN102.9 CN103.3 CN104.4 CN201.3 CN202.9 CN203.3 CN204.4 CN301.3 CN302.9 CN303.3 CN304.4 CN500.2 CN510.2 CN520.2 CN530.2 CN540.2 CN958.1 IC106.3 IC650.5 IC650.8 IC807.3 IC808.3 IC809.3 Q500.2(E) Q512.2(E) Q522.2(E) Q532.2(E) Q542.2(E) R505.1 R568.1 R578.1 R588.1 R598.1 R635.2 R636.2 R637.2 R648.2 R673.1 ; also on sheet 5
GND-1: C701.2 C702.2 CN959.1 IC651.3 IC651.7 J826.2 R674.1 ; also on sheet 1 2 3 4
GND_P0: CN1.6 CN3.1 CN103.1 CN203.1 CN303.1 ; also on sheet 5 6
GND_P1: CN101.6 ; also on sheet 6
GND_P2: CN201.6 ; also on sheet 6
GND_P3: CN301.6 ; also on sheet 6
VDD: C665.2 C666.2 C667.1 C668.1 C669.1 C670.1 C671.2 C672.2 C673.2 C674.2 IC600.16 IC600.21 IC600.61 IC600.76 IC600.117 IC600.126 IC600.137 IC600.153 IC600.158 IC600.169 IC621.3 J804.2
VDDA: C660.2 C663.1(2) C676.2 C678.1 CN4.5 CN104.5 CN204.5 CN304.5 IC600.36 IC600.54 J827.1 L654.2 ; also on sheet 1 2 3 4
VDDIO: C620.1 C621.1 C658.2 C661.2 C664.1(2) C680.2 C681.2 C682.2 C683.2 C684.2 C685.1 C686.1 C687.1 C688.1 C689.1 C690.1 C691.1 C692.1 C693.1 C694.1 C695.2 C696.2 C697.2 C698.2 C699.2 C700.2 CN1.1 CN101.1 CN201.1 CN301.1 IC600.3 IC600.11 IC600.15 IC600.20 IC600.26 IC600.62 IC600.68 IC600.75 IC600.82 IC600.88 IC600.91 IC600.99 IC600.106 IC600.114 IC600.116 IC600.119 IC600.127 IC600.138 IC600.147 IC600.152 IC600.159 IC600.168 IC620.3 IC620.5 IC621.5 L652.2 R500.2 R502.2 R631.1 R632.2 R633.2 R655.1 R656.2 R657.2 R658.2
VDDOSC: C659.2 C662.1(2) C677.1 C679.1 IC600.120 IC600.125 L653.2
BIAS_1_ON-1: IC600.23 ; also on sheet 4
BIAS_1_ON-2: IC600.134 ; also on sheet 3
BIAS_1_ON-3: IC600.100 ; also on sheet 2
BIAS_1_ON-4: IC600.86 ; also on sheet 1
BIAS_2_ON-1: IC600.24 ; also on sheet 4
BIAS_2_ON-2: IC600.136 ; also on sheet 3
BIAS_2_ON-3: IC600.101 ; also on sheet 2
BIAS_2_ON-4: IC600.87 ; also on sheet 1
DIAG0-1: CN3.6 IC600.27 R515.2
DIAG0-2: CN103.6 IC600.130 R525.1
DIAG0-3: CN203.6 IC600.103 R535.1
DIAG0-4: CN303.6 IC600.141 R545.2
EN_1R2V: D620.2(C) IC620.1 J829.2 R632.1
H_EN_0-1: CN4.3 IC600.8
H_EN_0-2: CN104.3 IC600.67
H_EN_0-3: CN204.3 IC600.90
H_EN_0-4: CN304.3 IC600.110
I_H0-1: R510.2 ; also on sheet 4
I_H0-2: R520.2 ; also on sheet 3
I_H0-3: R530.2 ; also on sheet 2
I_H0-4: R540.2 ; also on sheet 1
I_L0-1: R511.1 ; also on sheet 4
I_L0-2: R521.1 ; also on sheet 3
I_L0-3: R531.1 ; also on sheet 2
I_L0-4: R541.1 ; also on sheet 1
I_SEL_1: IC106.4 ; also on sheet 4
I_SEL_2: IC807.4 ; also on sheet 3
I_SEL_3: IC808.4 ; also on sheet 2
I_SEL_4: IC809.4 ; also on sheet 1
I_SEL_CM-1: IC600.14 R506.2 ; also on sheet 4
I_SEL_CM-2: IC600.71 R614.1 ; also on sheet 3
I_SEL_CM-3: IC600.95 R620.1 ; also on sheet 2
I_SEL_CM-4: IC600.111 R623.1 ; also on sheet 1
L_IN1_0-1: CN3.4 IC600.13
L_IN1_0-2: CN103.4 IC600.83
L_IN1_0-3: CN203.4 IC600.96
L_IN1_0-4: CN303.4 IC600.133
MES_EN_0-1: CN2.8 IC600.10
MES_EN_0-2: CN102.8 IC600.70
MES_EN_0-3: CN202.8 IC600.94
MES_EN_0-4: CN302.8 IC600.112
PowrGood_0-1: CN4.1 IC600.25 R514.2
PowrGood_0-2: CN104.1 IC600.89 R524.1
PowrGood_0-3: CN204.1 IC600.102 R534.1
PowrGood_0-4: CN304.1 IC600.140 R544.2
PWM_H_0-1: CN2.2 IC600.160 R551.2
PWM_H_0-2: CN102.2 IC600.164 R552.2
PWM_H_0-3: CN202.2 IC600.1 R553.2
PWM_H_0-4: CN302.2 IC600.4 R554.2
PWM_L_0-1: CN2.1 IC600.161 R556.2
PWM_L_0-2: CN102.1 IC600.165 R557.2
PWM_L_0-3: CN202.1 IC600.2 R558.2
PWM_L_0-4: CN302.1 IC600.5 R559.2
SIG0026: DS531.2(C) Q530.3
SIG0027: DS530.2(C) Q530.6
SIG0028: DS533.2(C) Q531.3
SIG0029: DS532.2(C) Q531.6
SIG0034: DS540.2(C) Q540.6
SIG0036: DS542.2(C) Q541.6
SIG0037: DS540.1(A) R546.1
SIG0038: DS543.1(A) R549.1
SIG0039: DS542.1(A) R548.1
SIG0042: Q500.1(B) R504.2 R505.2
SIG0043: C502.2 R502.1 R503.2
SIG0044: C500.1 C501.2
SIG0045: C500.2 CN500.1 R501.1
SIG0047: R501.2 R503.1 R504.1
SIG0048: IC600.155 Q500.3(C) R500.1
SIG00215: DS511.1(A) R517.1
SIG00216: DS512.1(A) R518.1
SIG00217: DS510.1(A) R516.1
SIG00218: DS512.2(C) Q511.6
SIG00219: DS510.2(C) Q510.6
SIG00220: DS513.2(C) Q511.3
SIG00223: DS511.2(C) Q510.3
SIG00226: DS513.1(A) R519.1
SIG00236: IC600.65 Q510.5
SIG00237: IC600.64 Q510.2
SIG00238: IC600.66 Q511.5
SIG00239: IC600.63 Q511.2
SIG00310: DS541.1(A) R547.1
SIG00311: DS543.2(C) Q541.3
SIG00313: DS541.2(C) Q540.3
SIG00314: IC600.144 Q540.5
SIG00315: IC600.143 Q540.2
SIG00316: IC600.146 Q541.5
SIG00317: IC600.145 Q541.2
SIG00319: C546.2 CN540.1 R594.1
SIG00320: Q542.1(B) R597.2 R598.2
SIG00321: C548.2 R595.1 R596.2
SIG00323: R594.2 R596.1 R597.1
SIG00325: Q522.1(B) R577.2 R578.2
SIG00326: C526.2 CN520.1 R574.1
SIG00328: C528.2 R575.1 R576.2
SIG00329: R574.2 R576.1 R577.1
SIG00330: IC600.142 Q542.3(C) R599.1
SIG00331: IC600.131 Q522.3(C) R579.1
SIG00337: DS521.1(A) R527.1
SIG00339: DS520.1(A) R526.1
SIG00340: DS523.2(C) Q521.3
SIG00342: DS521.2(C) Q520.3
SIG00343: DS520.2(C) Q520.6
SIG00344: DS522.1(A) R528.1
SIG00345: DS523.1(A) R529.1
SIG00346: DS522.2(C) Q521.6
SIG00348: IC600.115 Q520.5
SIG00349: IC600.113 Q520.2
SIG00350: IC600.129 Q521.5
SIG00351: IC600.128 Q521.2
SIG00354: C622.2 D620.1(A) IC600.124 IC621.1 R633.1
SIG569: IC600.9 R608.2
SIG570: IC600.6 R606.2
SIG571: IC600.7 R607.2
SIG572: IC600.12 R609.2
SIG573: IC600.17 R646.2
SIG574: IC600.18 R604.2
SIG575: IC600.19 R605.2
SIG592: C532.2 IC600.31 R532.2
SIG593: C525.2 IC600.38 R573.2
SIG595: C512.2 IC600.44 R512.1
SIG597: C520.2 IC600.42 R520.1
SIG598: C530.2 IC600.41 R530.1
SIG599: C540.2 IC600.40 R540.1
SIG606: C542.2 IC600.30 R542.2
SIG608: C545.2 IC600.29 R593.2
SIG611: C544.2 CN305.1 R592.2 R593.1
SIG613: C524.2 CN105.1 R572.2 R573.1
SIG616: C514.2 CN5.1 R562.2 R563.1
SIG623: C510.2 IC600.43 R510.1
SIG626: C531.1 IC600.48 R531.2
SIG627: C541.1 IC600.49 R541.2
SIG628: C521.1 IC600.47 R521.2
SIG629: C511.1 IC600.46 R511.2
SIG630: C522.1 IC600.45 R522.2
SIG634: C515.2 IC600.39 R563.2
SIG635: C606.1 R664.2
SIG636: C604.1 R662.2
SIG638: C535.1 IC600.60 R583.1
SIG639: C543.1 IC600.59 R543.2
SIG640: C533.1 IC600.58 R533.2
SIG641: C523.1 IC600.57 R523.2
SIG642: C513.1 IC600.56 R513.2
SIG665: IC600.69 R613.1
SIG669: IC600.78 R659.1
SIG671: IC600.84 R507.1
SIG674: CN620.2 IC600.79 R669.2
SIG675: CN620.3 IC600.77
SIG676: CN620.7 R659.2
SIG677: CN620.1 IC600.80
SIG678: CN620.9 CN620.11 IC600.81
SIG680: CN620.14 R658.1
SIG681: CN620.13 R657.1
SIG682: CN620.5 R656.1
SIG686: IC600.93 R618.1
SIG689: IC600.97 R508.1
SIG694: IC600.28 Q512.3(C) R569.1
SIG697: Q512.1(B) R567.2 R568.2
SIG698: R564.2 R566.1 R567.1
SIG700: C518.2 R565.1 R566.2
SIG701: C516.1 C517.2
SIG702: C516.2 CN510.1 R564.1
SIG705: R584.1 R586.1 R587.2
SIG706: C536.2 CN530.1 R584.2
SIG709: Q532.1(B) R587.1 R588.2
SIG710: IC600.104 Q532.3(C) R589.1
SIG713: DS530.1(A) R536.1
SIG715: DS533.1(A) R539.1
SIG717: DS531.1(A) R537.1
SIG719: DS532.1(A) R538.1
SIG724: IC600.105 Q530.2
SIG725: IC600.107 Q530.5
SIG726: IC600.108 Q531.2
SIG727: IC600.109 Q531.5
SIG729: C538.2 R585.1 R586.2
SIG738: IC600.118 R647.1
SIG779: IC600.132 R624.1
SIG780: IC600.139 R631.2
SIG819: IC106.2 IC600.148 R648.1
SIG825: IC600.149 IC807.2 R635.1
SIG848: IC600.150 IC808.2 R636.1
SIG849: IC600.151 IC809.2 R637.1
SIG850: IC600.154 R655.2
SIG852: IC600.156 R638.2
SIG853: IC600.157 R639.2
SIG855: IC600.163 R601.2
SIG856: IC600.162 R600.2
SIG857: IC600.167 R603.2
SIG858: IC600.166 R602.2
SIG859: IC600.170 R640.2
SIG860: IC600.171 R641.2
SIG861: IC600.172 R642.2
SIG862: IC600.175 R634.2
SIG863: IC600.174 R644.2
SIG864: IC600.173 R643.2
SIG865: IC600.176 R645.2
SIG889: IC650.4 L650.1
SIG891: IC650.1 R671.1 R673.2
SIG893: C652.2 IC650.3 J803.1 L650.2 R670.2 TP804.1
SIG894: IC651.2 R674.2
SIG895: IC651.6 L656.1
SIG896: IC651.10 L651.1
SIG898: C704.1 IC651.1 R678.1 R679.2
SIG901: R675.2 R676.1
SIG902: IC651.5 R675.1 R677.2
SIG903: IC651.9 J829.1 TP806.1
SIG905: C703.2 C704.2 CN963.1 D650.1(A) J804.1 L651.2 R672.2 R678.2
SIG909: C705.2 CN964.1 D650.2(C) IC651.4 J805.1 L656.2 R676.2
SIG914: C600.2 C603.2 IC601.4 J827.2 R660.2
SIG916: C601.2 IC602.1 R660.1 R661.1
SIG918: C602.2 IC601.3 IC601.5 IC601.10 IC601.12 R661.2
STBY_0-1: CN3.5 IC600.22
STBY_0-2: CN103.5 IC600.85
STBY_0-3: CN203.5 IC600.98
STBY_0-4: CN303.5 IC600.135
TH-2: C534.2 CN205.1 R582.2 R583.2
V_B0-1: CN2.7 R512.2
V_B0-2: CN102.7 R522.1
V_B0-3: CN202.7 R532.1
V_B0-4: CN302.7 R542.1
V_C0-1: CN2.6 R513.1
V_C0-2: CN102.6 R523.1
V_C0-3: CN202.6 R533.1
V_C0-4: CN302.6 R543.1
VP_3R3V_SYS: C654.2 C655.2 C656.2 C675.1 IC600.72 J805.2 L652.1 L653.1 L654.1 R514.1 R515.1 R524.2 R525.2 R534.2 R535.2 R544.1 R545.1 R565.2 R569.2 R575.2 R579.2 R585.2 R589.2 R595.2 R599.2
VP_5R0: C635.2 C636.2 C637.2 C648.2 CN1.2 CN101.2 CN201.2 CN301.2 IC106.5 IC807.5 IC808.5 IC809.5 J803.2 J826.1 R516.2 R517.2 R518.2 R519.2 R526.2 R527.2 R528.2 R529.2 R536.2 R537.2 R538.2 R539.2 R546.2 R547.2 R548.2 R549.2
VP_5V_I0_0: CN1.4 ; also on sheet 6
VP_5V_I0_1: CN3.2 ; also on sheet 6
VP_5V_I0_2: CN4.2 ; also on sheet 6
VP_5V_I1_0: CN101.4 ; also on sheet 6
VP_5V_I1_1: CN103.2 ; also on sheet 6
VP_5V_I1_2: CN104.2 ; also on sheet 6
VP_5V_I2_0: CN201.4 ; also on sheet 6
VP_5V_I2_1: CN203.2 ; also on sheet 6
VP_5V_I2_2: CN204.2 ; also on sheet 6
VP_5V_I3_0: CN301.4 ; also on sheet 6
VP_5V_I3_1: CN303.2 ; also on sheet 6
VP_5V_I3_2: CN304.2 ; also on sheet 6
VP_12R0_SYS: C650.1(2) C651.2 CN957.1 IC650.6 IC650.7 ; also on sheet 5 6
VP_12R0_SYS_I0_0: CN1.5 ; also on sheet 6
VP_12R0_SYS_I0_1: CN3.7 ; also on sheet 6
VP_12R0_SYS_I1_0: CN101.5 ; also on sheet 6
VP_12R0_SYS_I1_1: CN103.7 ; also on sheet 6
VP_12R0_SYS_I2_0: CN201.5 ; also on sheet 6
VP_12R0_SYS_I2_1: CN203.7 ; also on sheet 6
VP_12R0_SYS_I3_0: CN301.5 ; also on sheet 6
VP_12R0_SYS_I3_1: CN303.7 ; also on sheet 6
VP_L_0: CN3.8 ; also on sheet 5
VP_L_1: CN103.8 ; also on sheet 5
VP_L_2: CN203.8 ; also on sheet 5
VP_L_3: CN303.8 ; also on sheet 5
VREF_A: IC600.37 IC601.1 IC601.2 R562.1 R572.1 R665.2
VREF_B: IC600.53 IC601.6 IC601.7 R664.1
VREF_C: IC600.35 IC601.8 IC601.9 R592.1 R663.2
VREF_D: IC600.55 IC601.13 IC601.14 R582.1 R662.1
N03443: C607.2 R665.1
N03444: C605.2 R663.1
N06036: C536.1 C537.2
N08819: C546.1 C547.2
N08820: C526.1 C527.2

Not connected (* = marked no-connect by the designer): CN2 3 4 5; CN102 3 4 5; CN202 3 4 5; CN302 3 4 5; CN620 6; IC106 1; IC600 73 74 92 121; IC602 3; IC620 6; IC621 6; IC650 2; IC807 1; IC808 1; IC809 1

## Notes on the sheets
sheet 7
- X3
- ¦GND is connected to DGND
- X2
- X2
- 1/4
- 2/4
- 3/4
- 4/4
sheet 8
- ¦CN1 is connected to CN1 of RD210-SCHEMATIC1
- ¦CN4 is connected to CN4 of RD210-SCHEMATIC1
- ¦CN101 is connected to CN101 of RD210-SCHEMATIC1
- ¦CN104 is connected to CN104 of RD210-SCHEMATIC1
- ¦CN201 is connected to CN201 of RD210-SCHEMATIC1
- ¦CN204 is connected to CN204 of RD210-SCHEMATIC1
- ¦CN301 is connected to CN301 of RD210-SCHEMATIC1
- ¦CN304 is connected to CN304 of RD210-SCHEMATIC1
- ¦CN2 is connected to CN2 of RD210-SCHEMATIC1
- ¦CN3 is connected to CN3 of RD210-SCHEMATIC1
- ¦CN102 is connected to CN102 of RD210-SCHEMATIC1
- ¦CN103 is connected to CN103 of RD210-SCHEMATIC1
- ¦CN202 is connected to CN202 of RD210-SCHEMATIC1
- ¦CN203 is connected to CN203 of RD210-SCHEMATIC1
- ¦CN302 is connected to CN302 of RD210-SCHEMATIC1
- ¦CN303 is connected to CN303 of RD210-SCHEMATIC1
sheet 9
- ¦AGND is connected to DGND
sheet 12
- ¦  CN5 is connected to CN5 of RD210-SCHEMATIC1
- ¦CN105 is connected to CN105 of RD210-SCHEMATIC1
- ¦CN205 is connected to CN205 of RD210-SCHEMATIC1
- ¦CN305 is connected to CN305 of RD210-SCHEMATIC1
